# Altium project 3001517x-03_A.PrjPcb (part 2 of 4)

## Sheet 05 - JTAG, SWD, Console, UART, IO expander.SchDoc: JTAG, SWD, Console, UART
size A3; PageSetup: Record=PageOptions¦CenterHorizontal=True¦CenterVertical=True¦PrintScale=0.70¦XCorrection=1.00¦YCorrection=1.00¦PrintKind=0¦BorderSize=5000000¦LeftOffset=0¦BottomOffset=0¦Orientation=2¦PaperLength=4200¦PaperWidth=2970¦Scale=100¦PaperSource=7¦PrintQuality=600¦MediaType=1¦DitherType=10¦PaperKind=A4¦PrintScaleMode=1; Author: Sébastien MEYER; SheetNumber: 5; SheetTotal: 14
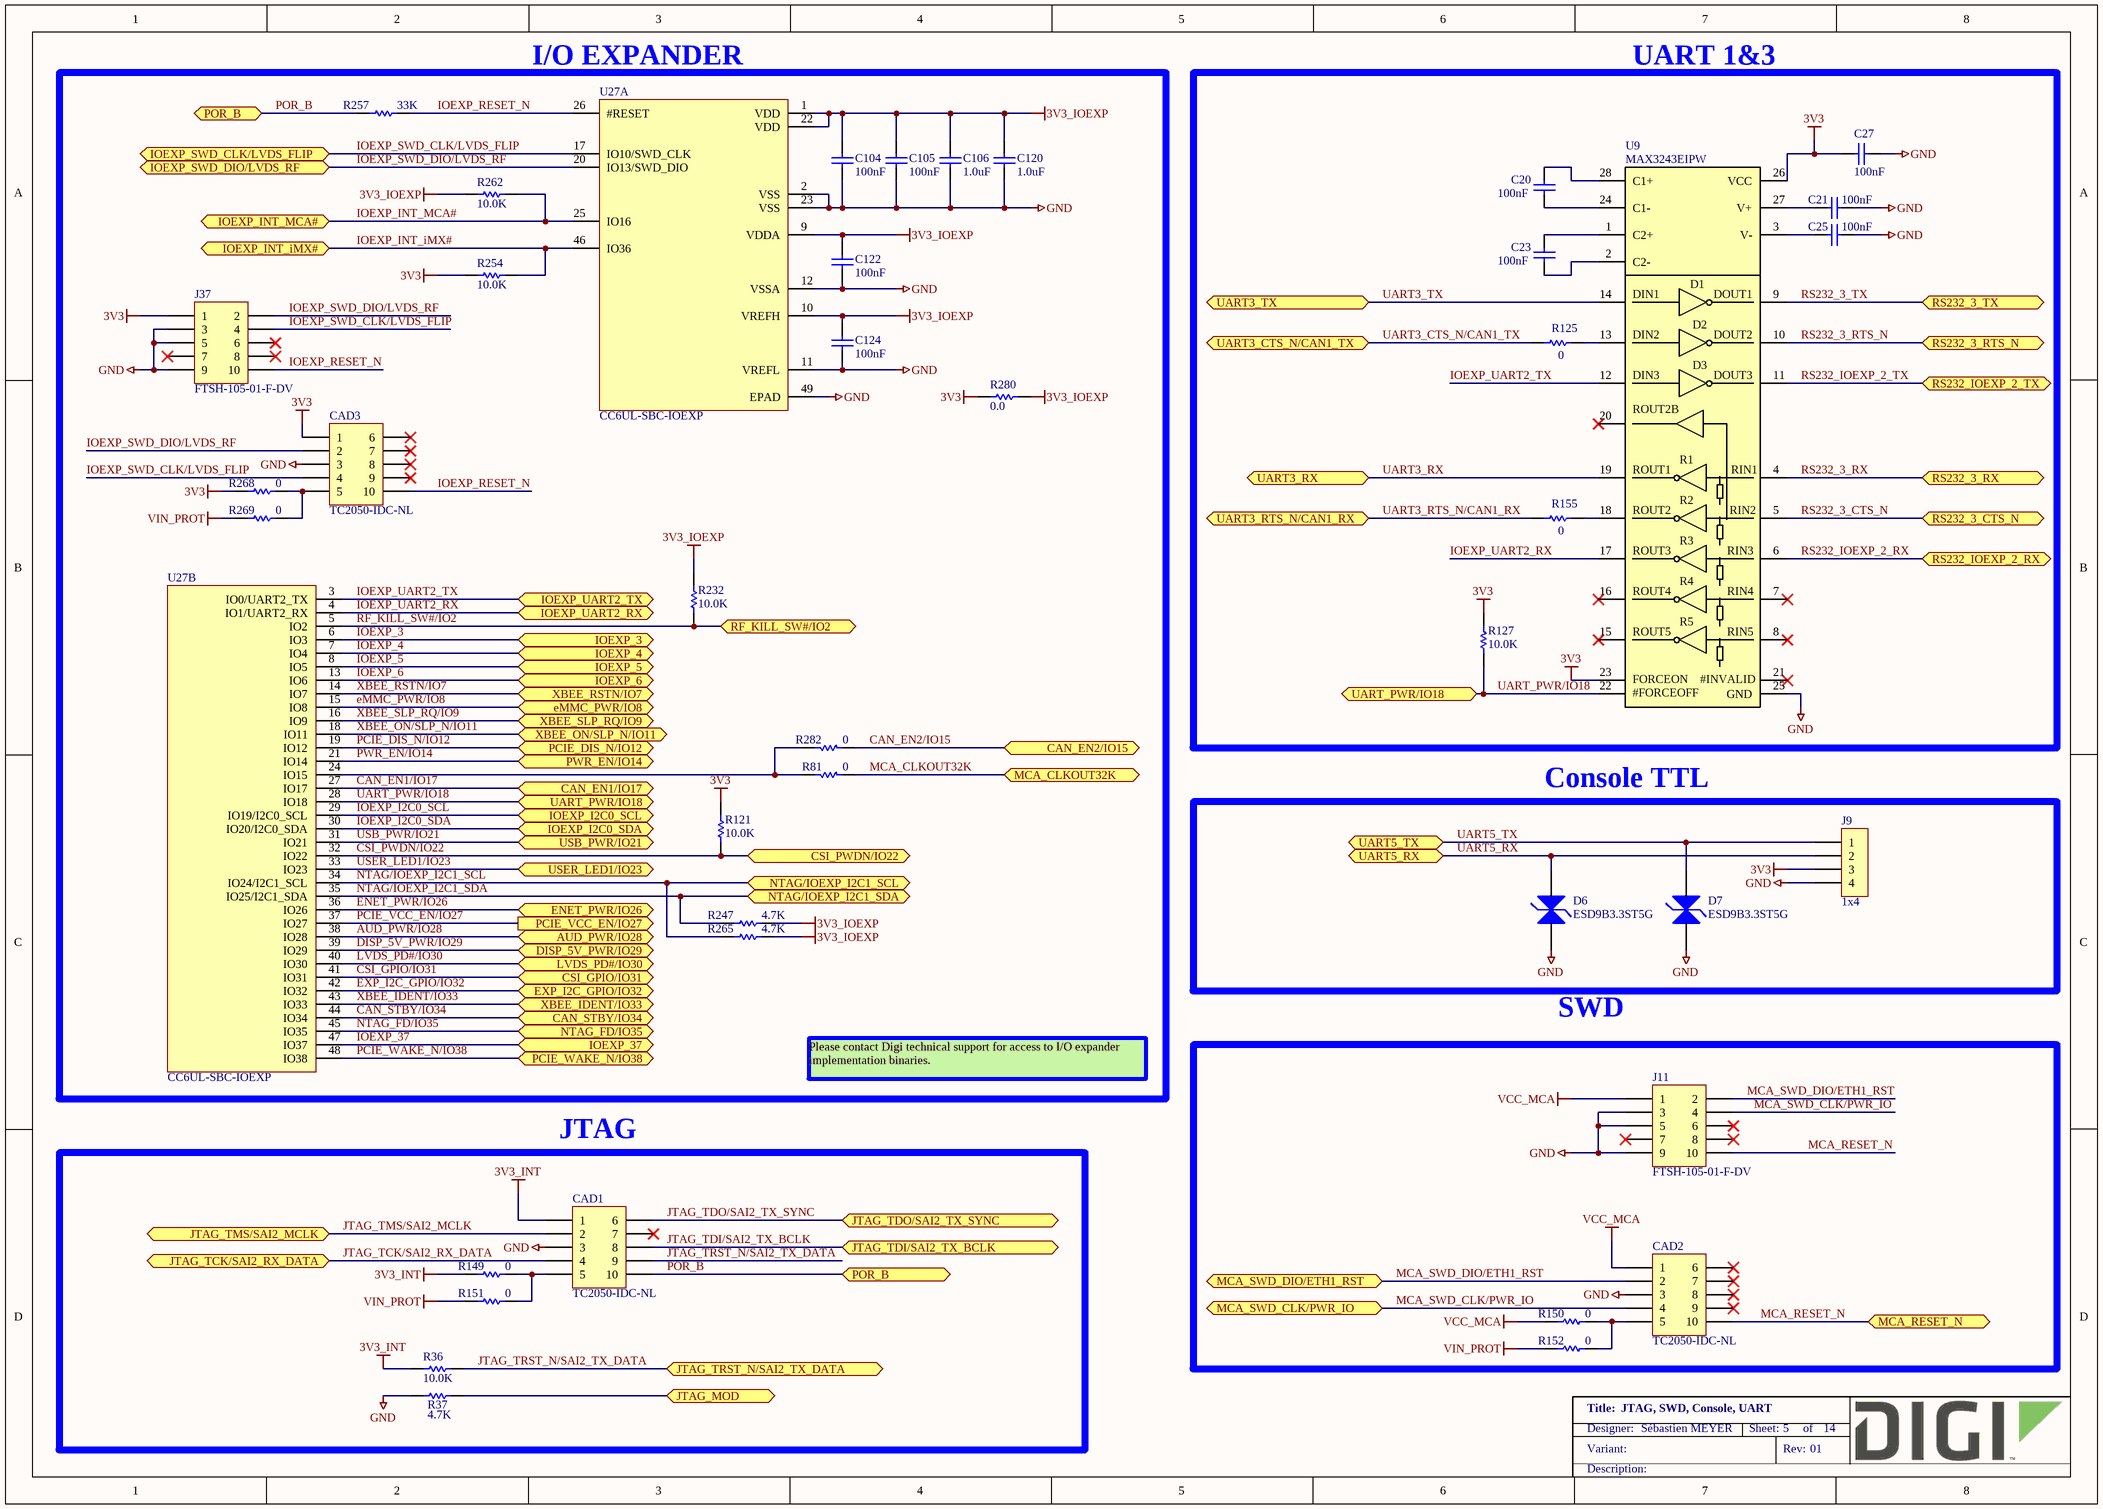
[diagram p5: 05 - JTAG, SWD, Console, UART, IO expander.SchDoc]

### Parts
C20  100nF  [CAPC1005X55N]
C21  100nF  [CAPC1005X55N]
C23  100nF  [CAPC1005X55N]
C25  100nF  [CAPC1005X55N]
C27  100nF  [CAPC1005X55N]
C104  100nF  [CAPC1005X55N]
C105  100nF  [CAPC1005X55N]
C106  1.0uF  [CAPC1005X55AL]
C120  1.0uF  [CAPC1005X55AL]
C122  100nF  [CAPC1005X55N]
C124  100nF  [CAPC1005X55N]
CAD1  TC2050-IDC-NL  [TC_TC2050-IDC-NL]  (no BOM)
CAD2  TC2050-IDC-NL  [TC_TC2050-IDC-NL]  (no BOM)
CAD3  TC2050-IDC-NL  [TC_TC2050-IDC-NL]  (no BOM)
D6  ESD9B3.3ST5G  [SODFL1006X43AN12]
D7  ESD9B3.3ST5G  [SODFL1006X43AN12]
J9  1x4  [MOLEX_53047-0410]
J11  FTSH-105-01-F-DV  [SAMTEC_FTSH-105-01-F-DV]
J37  FTSH-105-01-F-DV  [SAMTEC_FTSH-105-01-F-DV]
R36  10.0K  [RESC1005X40N]
R37  4.7K  [RESC1005X40N]
R81  0  [RESC1005X40N]
R121  10.0K  [RESC1005X40N]
R125  0  [RESC1005X40N]
R127  10.0K  [RESC1005X40N]
R149  0  [RESC1005X40N]
R150  0  [RESC1005X40N]
R151  0  [RESC1005X40N]
R152  0  [RESC1005X40N]
R155  0  [RESC1005X40N]
R232  10.0K  [RESC1005X40N]
R247  4.7K  [RESC1005X40N]
R254  10.0K  [RESC1005X40N]
R257  33K  [RESC1005X40N]
R262  10.0K  [RESC1005X40N]
R265  4.7K  [RESC1005X40N]
R268  0  [RESC1005X40N]
R269  0  [RESC1005X40N]
R280  0.0  [RESC2013X70N]
R282  0  [RESC1005X40N]
U9  MAX3243EIPW  [SOP65P640X120-28N]
U27  CC6UL-SBC-IOEXP  [QFN50P700X700X100-49N]  (parts A,B of 2)

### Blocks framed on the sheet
I/O EXPANDER: C104-C106 C120 C122 C124 CAD3 J37 R81 R121 R232 R247 R254 R257 R262 R265 R268 R269 R280 R282 U27
UART 1&3: C20 C21 C23 C25 C27 R125 R127 R155 U9
Console TTL: D6 D7 J9
JTAG: CAD1 R36 R37 R149 R151

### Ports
AUD_PWR/IO28 (bidir), CAN_EN1/IO17 (bidir), CAN_EN2/IO15 (bidir), CAN_STBY/IO34 (bidir), CSI_GPIO/IO31 (bidir), CSI_PWDN/IO22 (bidir), DISP_5V_PWR/IO29 (bidir), eMMC_PWR/IO8 (bidir), ENET_PWR/IO26 (bidir), EXP_I2C_GPIO/IO32 (bidir), IOEXP_3 (bidir), IOEXP_4 (bidir), IOEXP_5 (bidir), IOEXP_6 (bidir), IOEXP_37 (bidir), IOEXP_I2C0_SCL (bidir), IOEXP_I2C0_SDA (bidir), IOEXP_INT_iMX# (bidir), IOEXP_INT_MCA# (bidir), IOEXP_SWD_CLK/LVDS_FLIP (bidir), IOEXP_SWD_DIO/LVDS_RF (bidir), IOEXP_UART2_RX (bidir), IOEXP_UART2_TX (bidir), JTAG_MOD (bidir), JTAG_TCK/SAI2_RX_DATA (bidir), JTAG_TDI/SAI2_TX_BCLK (bidir), JTAG_TDO/SAI2_TX_SYNC (bidir), JTAG_TMS/SAI2_MCLK (bidir), JTAG_TRST_N/SAI2_TX_DATA (bidir), LVDS_PD#/IO30 (bidir), MCA_CLKOUT32K (bidir), MCA_RESET_N (bidir), MCA_SWD_CLK/PWR_IO (bidir), MCA_SWD_DIO/ETH1_RST (bidir), NTAG/IOEXP_I2C1_SCL (bidir), NTAG/IOEXP_I2C1_SDA (bidir), NTAG_FD/IO35 (bidir), PCIE_DIS_N/IO12 (bidir), PCIE_VCC_EN/IO27 (out), PCIE_WAKE_N/IO38 (bidir), POR_B (bidir), PWR_EN/IO14 (bidir), RF_KILL_SW#/IO2 (bidir), RS232_3_CTS_N (bidir), RS232_3_RTS_N (bidir), RS232_3_RX (bidir), RS232_3_TX (bidir), RS232_IOEXP_2_RX (bidir), RS232_IOEXP_2_TX (bidir), UART3_CTS_N/CAN1_TX (bidir), UART3_RTS_N/CAN1_RX (bidir), UART3_RX (bidir), UART3_TX (bidir), UART5_RX (bidir), UART5_TX (bidir), UART_PWR/IO18 (bidir), USB_PWR/IO21 (bidir), USER_LED1/IO23 (bidir), XBEE_IDENT/IO33 (bidir), XBEE_ON/SLP_N/IO11 (bidir), XBEE_RSTN/IO7 (bidir), XBEE_SLP_RQ/IO9 (bidir)

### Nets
3V3: C27.2 CAD3.1 J9.3 J37.1 R121.2 R127.1 R254.1 R268.1 R280.1 U9.23(FORCEON) U9.26(VCC)
3V3_INT: CAD1.1 R36.2 R149.1
3V3_IOEXP: C104.2 C105.2 C106.2 C120.2 C122.2 C124.2 R232.1 R247.2 R262.2 R265.2 R280.2 U27.1(VDD) U27.9(VDDA) U27.10(VREFH) U27.22(VDD)
GND: C21.1 C25.1 C27.1 C104.1 C105.1 C106.1 C120.1 C122.1 C124.1 CAD1.3 CAD2.3 CAD3.3 D6.1 D7.1 J9.4 J11.3 J11.5 J11.9 J37.3 J37.5 J37.9 R37.1 U9.25(GND) U27.2(VSS) U27.11(VREFL) U27.12(VSSA) U27.23(VSS) U27.49(EPAD)
VCC_MCA: CAD2.1 J11.1 R150.1
VIN_PROT: R151.1 R152.1 R269.1
AUD_PWR/IO28: U27.38(IO28) ; port AUD_PWR/IO28
CAN_EN1/IO17: U27.27(IO17) ; port CAN_EN1/IO17
CAN_EN2/IO15: R282.1 ; port CAN_EN2/IO15
CAN_STBY/IO34: U27.44(IO34) ; port CAN_STBY/IO34
CSI_GPIO/IO31: U27.41(IO31) ; port CSI_GPIO/IO31
CSI_PWDN/IO22: R121.1 U27.32(IO22) ; port CSI_PWDN/IO22
DISP_5V_PWR/IO29: U27.39(IO29) ; port DISP_5V_PWR/IO29
eMMC_PWR/IO8: U27.15(IO8) ; port eMMC_PWR/IO8
ENET_PWR/IO26: U27.36(IO26) ; port ENET_PWR/IO26
EXP_I2C_GPIO/IO32: U27.42(IO32) ; port EXP_I2C_GPIO/IO32
IOEXP_3: U27.6(IO3) ; port IOEXP_3
IOEXP_4: U27.7(IO4) ; port IOEXP_4
IOEXP_5: U27.8(IO5) ; port IOEXP_5
IOEXP_6: U27.13(IO6) ; port IOEXP_6
IOEXP_37: U27.47(IO37) ; port IOEXP_37
IOEXP_I2C0_SCL: U27.29(IO19/I2C0_SCL) ; port IOEXP_I2C0_SCL
IOEXP_I2C0_SDA: U27.30(IO20/I2C0_SDA) ; port IOEXP_I2C0_SDA
IOEXP_INT_iMX#: R254.2 U27.46(IO36) ; port IOEXP_INT_iMX#
IOEXP_INT_MCA#: R262.1 U27.25(IO16) ; port IOEXP_INT_MCA#
IOEXP_RESET_N: CAD3.10 J37.10 R257.2 U27.26(#RESET)
IOEXP_SWD_CLK/LVDS_FLIP: CAD3.4 J37.4 U27.17(IO10/SWD_CLK) ; port IOEXP_SWD_CLK/LVDS_FLIP
IOEXP_SWD_DIO/LVDS_RF: CAD3.2 J37.2 U27.20(IO13/SWD_DIO) ; port IOEXP_SWD_DIO/LVDS_RF
IOEXP_UART2_RX: U9.17(ROUT3) U27.4(IO1/UART2_RX) ; port IOEXP_UART2_RX
IOEXP_UART2_TX: U9.12(DIN3) U27.3(IO0/UART2_TX) ; port IOEXP_UART2_TX
JTAG_MOD: R37.2 ; port JTAG_MOD
JTAG_TCK/SAI2_RX_DATA: CAD1.4 ; port JTAG_TCK/SAI2_RX_DATA
JTAG_TDI/SAI2_TX_BCLK: CAD1.8 ; port JTAG_TDI/SAI2_TX_BCLK
JTAG_TDO/SAI2_TX_SYNC: CAD1.6 ; port JTAG_TDO/SAI2_TX_SYNC
JTAG_TMS/SAI2_MCLK: CAD1.2 ; port JTAG_TMS/SAI2_MCLK
JTAG_TRST_N/SAI2_TX_DATA: CAD1.9 R36.1 ; port JTAG_TRST_N/SAI2_TX_DATA
LVDS_PD#/IO30: U27.40(IO30) ; port LVDS_PD#/IO30
MCA_CLKOUT32K: R81.1 ; port MCA_CLKOUT32K
MCA_RESET_N: CAD2.10 J11.10 ; port MCA_RESET_N
MCA_SWD_CLK/PWR_IO: CAD2.4 J11.4 ; port MCA_SWD_CLK/PWR_IO
MCA_SWD_DIO/ETH1_RST: CAD2.2 J11.2 ; port MCA_SWD_DIO/ETH1_RST
NTAG/IOEXP_I2C1_SCL: R265.1 U27.34(IO24/I2C1_SCL) ; port NTAG/IOEXP_I2C1_SCL
NTAG/IOEXP_I2C1_SDA: R247.1 U27.35(IO25/I2C1_SDA) ; port NTAG/IOEXP_I2C1_SDA
NTAG_FD/IO35: U27.45(IO35) ; port NTAG_FD/IO35
PCIE_DIS_N/IO12: U27.19(IO12) ; port PCIE_DIS_N/IO12
PCIE_VCC_EN/IO27: U27.37(IO27) ; port PCIE_VCC_EN/IO27
PCIE_WAKE_N/IO38: U27.48(IO38) ; port PCIE_WAKE_N/IO38
POR_B: CAD1.10 R257.1 ; port POR_B
PWR_EN/IO14: U27.21(IO14) ; port PWR_EN/IO14
RF_KILL_SW#/IO2: R232.2 U27.5(IO2) ; port RF_KILL_SW#/IO2
RS232_3_CTS_N: U9.5(RIN2) ; port RS232_3_CTS_N
RS232_3_RTS_N: U9.10(DOUT2) ; port RS232_3_RTS_N
RS232_3_RX: U9.4(RIN1) ; port RS232_3_RX
RS232_3_TX: U9.9(DOUT1) ; port RS232_3_TX
RS232_IOEXP_2_RX: U9.6(RIN3) ; port RS232_IOEXP_2_RX
RS232_IOEXP_2_TX: U9.11(DOUT3) ; port RS232_IOEXP_2_TX
UART3_CTS_N/CAN1_TX: R125.1 ; port UART3_CTS_N/CAN1_TX
UART3_RTS_N/CAN1_RX: R155.1 ; port UART3_RTS_N/CAN1_RX
UART3_RX: U9.19(ROUT1) ; port UART3_RX
UART3_TX: U9.14(DIN1) ; port UART3_TX
UART5_RX: D6.2 J9.2 ; port UART5_RX
UART5_TX: D7.2 J9.1 ; port UART5_TX
UART_PWR/IO18: R127.2 U9.22(#FORCEOFF) U27.28(IO18) ; port UART_PWR/IO18
USB_PWR/IO21: U27.31(IO21) ; port USB_PWR/IO21
USER_LED1/IO23: U27.33(IO23) ; port USER_LED1/IO23
XBEE_IDENT/IO33: U27.43(IO33) ; port XBEE_IDENT/IO33
XBEE_ON/SLP_N/IO11: U27.18(IO11) ; port XBEE_ON/SLP_N/IO11
XBEE_RSTN/IO7: U27.14(IO7) ; port XBEE_RSTN/IO7
XBEE_SLP_RQ/IO9: U27.16(IO9) ; port XBEE_SLP_RQ/IO9
NetC20_1: C20.1 U9.24(C1-)
NetC20_2: C20.2 U9.28(C1+)
NetC21_2: C21.2 U9.27(V+)
NetC23_1: C23.1 U9.2(C2-)
NetC23_2: C23.2 U9.1(C2+)
NetC25_2: C25.2 U9.3(V-)
NetCAD1_5: CAD1.5 R149.2 R151.2
NetCAD2_5: CAD2.5 R150.2 R152.2
NetCAD3_5: CAD3.5 R268.2 R269.2
NetR81_2: R81.2 R282.2 U27.24(IO15)
NetR125_2: R125.2 U9.13(DIN2)
NetR155_2: R155.2 U9.18(ROUT2)

Not connected (* = marked no-connect by the designer): CAD1 7*; CAD2 6* 7* 8* 9*; CAD3 6* 7* 8* 9*; J11 6* 7* 8*; J37 6* 7* 8*; U9 7(RI4N)* 8(RIN5)* 15(ROUT5)* 16(ROUT4)* 20(#R2OUT)* 21(#INVALID)*

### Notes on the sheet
- SWD
- Please contact Digi technical support for access to I/O expander implementation binaries.

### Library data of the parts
C20 C21 C23 C25 C27 C104 C105 C122 C124 = 1000006: CAP 100nF 16V 10% X7R 0402; Part_Type: Capacitor; Manufacturer: Murata; Manufacturer_Part_Number: GRM155R71C104KA88D; Component_Life_Cycle_State: CAD Reviewed; Area: 0.95; Project: KITT; Tolerance: 10; Digi_PN: 14050552
C106 C120 = 1000073: CAP CER 1UF 6.3V 20% X5R 0402; Part_Type: Capacitor; Manufacturer: Murata; Manufacturer_Part_Number: GRM155R60J105ME19D; Digi_PN: 14050543; Component_Life_Cycle_State: Proven; Area: 0.95; Project: Adjustable Foundation; Voltage: 6.3
CAD1-CAD3 = CAD0066: CBL PLUG-OF-NAILS 10-PIN; Part_Type: Test Point; Component_Life_Cycle_State: Created; Area: 8; Project: CCWMX6_SBC board
D6 D7 = 1001637: TVS DIODE 3.3VWM SOD923; Part_Type: Diodes; Manufacturer: On Semiconductor; Digi_PN: 17050883; Component_Life_Cycle_State: Reviewed; Area: 1,01; Project: CareTaker IV
J9 = 1001137: CONN HEADER 4POS 1.25MM VERT TIN; Part_Type: Connector; Manufacturer: Molex; Manufacturer_Part_Number: 53047-0410; Digi_PN: 18050344; Component_Life_Cycle_State: Reviewed; Area: 21,6; Project: CCWMX6_SBC board
J11 J37 = 1000034: CONN HEADER 10POS DUAL .05" SMD; Part_Type: Connector; Manufacturer: Samtec; Note: 18000715 = Digi No. for GE WDNU; Digi_PN: 18000539; Component_Life_Cycle_State: Proven; Area: 43,55; Project: Adjustable Foundation
R36 R121 R127 R232 R254 R262 = 1000537: RES 10.0K OHM 1/10W 1% 0402 SMD; Part_Type: Resistor; Manufacturer: Panasonic - ECG; Manufacturer_Part_Number: ERJ-2RKF1002X; Component_Life_Cycle_State: CAD Reviewed; Area: 0.95; Project: KITT; Power_WV_SRF: 100; Digi_PN: 13051084
R37 R247 R265 = 1000038: RES 4.7K OHM 1/10W 5% 0402 SMD; Part_Type: Resistor; Manufacturer: Panasonic - ECG; Manufacturer_Part_Number: ERJ-2GEJ472X; Component_Life_Cycle_State: Proven; Area: 0.95; Project: Adjustable Foundation; Power_WV_SRF: 100; Tolerance: 5; Digi_PN: 13050549
R81 R125 R149-R152 R155 R268 R269 R282 = 1000076: RES 0.0 OHM 1/10W 0402 SMD; Part_Type: Resistor; Manufacturer: Panasonic - ECG; Manufacturer_Part_Number: ERJ-2GE0R00X; Component_Life_Cycle_State: Proven; Area: 0.95; Project: Adjustable Foundation; Power_WV_SRF: 10; Digi_PN: 13050387
R257 = 1002118: RES SMD 33K OHM 1% 1/16W 0402; Part_Type: Resistor; Manufacturer: Panasonic - ECG; Manufacturer_Part_Number: ERJ-2RKF3302X; Component_Life_Cycle_State: Created; Area: 2,2; Project: iMX6UL+PMIC; Digi_PN: 13051142
R280 = 1001557: RES 0.0 OHM 1/8W JUMP 0805 SMD; Part_Type: Resistor; Manufacturer: Yageo; Manufacturer_Part_Number: RC0805JR-070RL; Note: 13051095 = Digi No. for GE WDNU; Digi_PN: TR00037; Component_Life_Cycle_State: Reviewed; Area: 5.8; Project: WDNU-II; Power_WV_SRF: 125
U9 = 1001499: IC RS232 3V-5.5V DRVR 28-TSSOP; Manufacturer: Texas Instruments; Digi_PN: 16050972; Component_Life_Cycle_State: Reviewed; Area: 67; Project: CCWMX6_SBC board
U27 = 1002077: KINETIS KL14, 32FL/4SR, -40/+105°C, QFN48; Part_Type: IC; Manufacturer: Freescale Semiconductor; Manufacturer_Part_Number: MKL14Z32VFT4; Digi_PN: 16051854; Component_Life_Cycle_State: Created; Area: 60,84; Project: iMX6UL+PMIC

## Sheet 06 - Ethernet.SchDoc: 2x 10/100M Ethernet
size A3; PageSetup: Record=PageOptions¦CenterHorizontal=True¦CenterVertical=True¦PrintScale=0.70¦XCorrection=1.00¦YCorrection=1.00¦PrintKind=0¦BorderSize=5000000¦LeftOffset=0¦BottomOffset=0¦Orientation=2¦PaperLength=4200¦PaperWidth=2970¦Scale=100¦PaperSource=7¦PrintQuality=600¦MediaType=1¦DitherType=10¦PaperKind=A4¦PrintScaleMode=1; Author: Sébastien MEYER; SheetNumber: 6; SheetTotal: 14
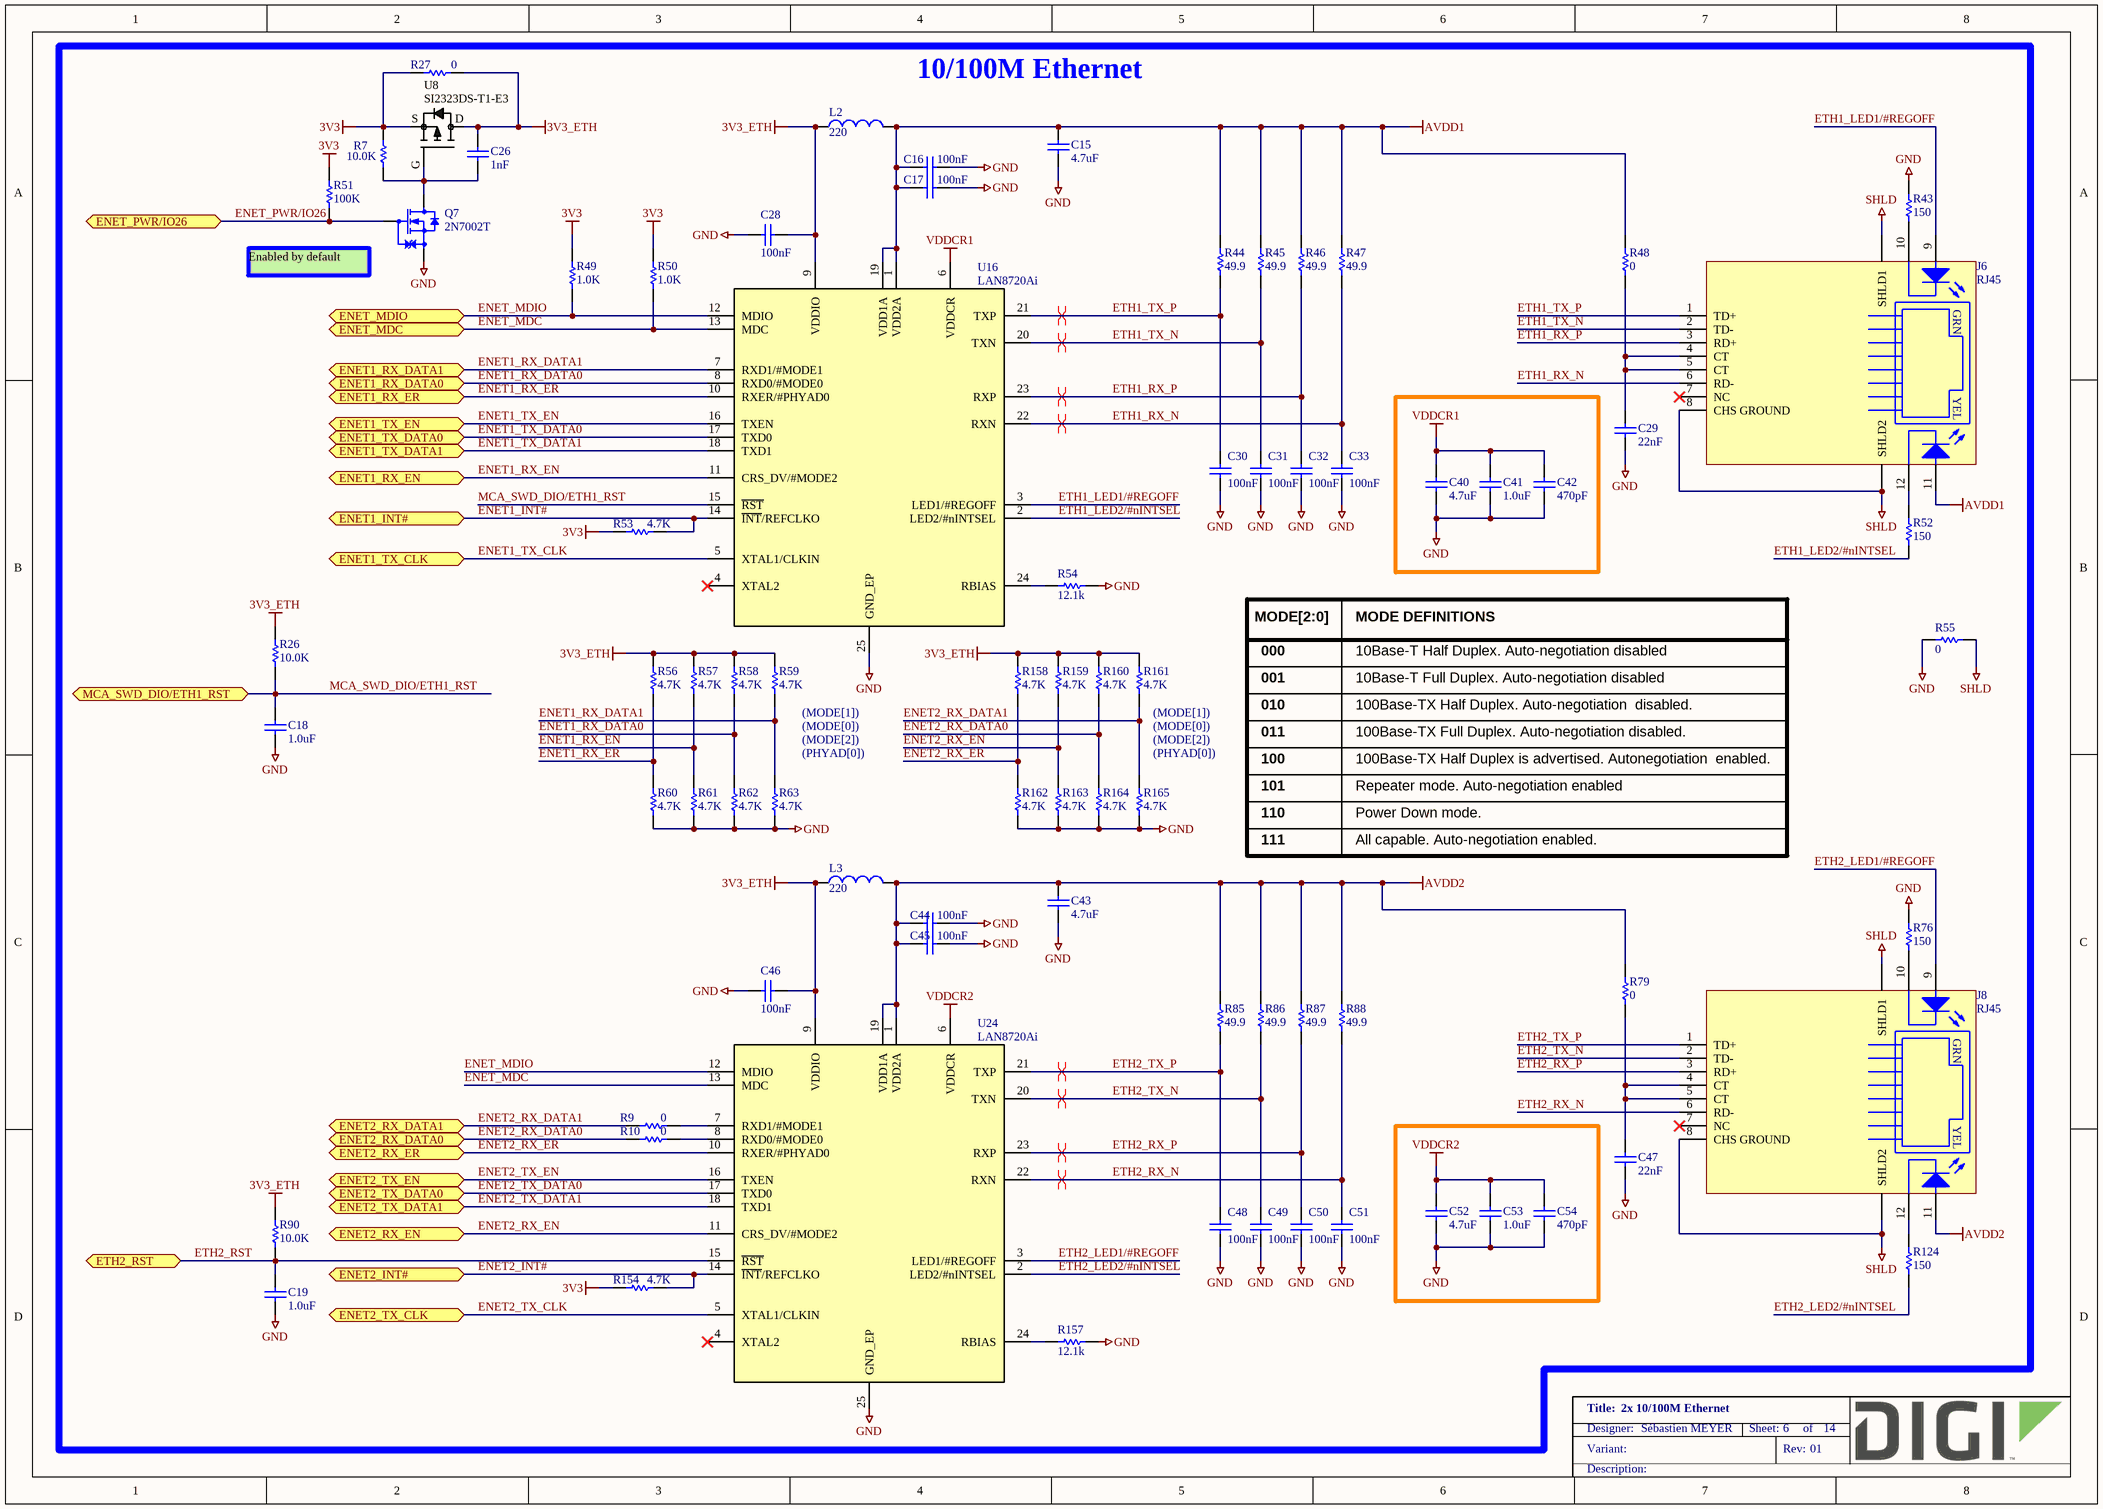
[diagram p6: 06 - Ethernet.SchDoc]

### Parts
C15  4.7uF  [CAPC2013X135N]
C16  100nF  [CAPC1005X55N]
C17  100nF  [CAPC1005X55N]
C18  1.0uF  [CAPC1005X55N]
C19  1.0uF  [CAPC1005X55N]
C26  1nF  [CAPC1005X55N]
C28  100nF  [CAPC1005X55N]
C29  22nF  [CAPC1608X90N]
C30  100nF  [CAPC1005X55N]
C31  100nF  [CAPC1005X55N]
C32  100nF  [CAPC1005X55N]
C33  100nF  [CAPC1005X55N]
C40  4.7uF  [CAPC2013X135N]
C41  1.0uF  [CAPC1005X55N]
C42  470pF  [CAPC1005X55N]
C43  4.7uF  [CAPC2013X135N]
C44  100nF  [CAPC1005X55N]
C45  100nF  [CAPC1005X55N]
C46  100nF  [CAPC1005X55N]
C47  22nF  [CAPC1608X90N]
C48  100nF  [CAPC1005X55N]
C49  100nF  [CAPC1005X55N]
C50  100nF  [CAPC1005X55N]
C51  100nF  [CAPC1005X55N]
C52  4.7uF  [CAPC2013X135N]
C53  1.0uF  [CAPC1005X55N]
C54  470pF  [CAPC1005X55N]
J6  RJ45  [XMultiple_XMG-9799-8821]
J8  RJ45  [XMultiple_XMG-9799-8821]
L2  220  [INDC2013X110N]
L3  220  [INDC2013X110N]
Q7  2N7002T  [SOTFL50P160X80_GSD-3N]
R7  10.0K  [RESC1005X40N]
R9  0  [RESC1005X40N]
R10  0  [RESC1005X40N]
R26  10.0K  [RESC1005X40N]
R27  0  [RESC1609X55N]
R43  150  [RESC1005X40N]
R44  49.9  [RESC1005X40N]
R45  49.9  [RESC1005X40N]
R46  49.9  [RESC1005X40N]
R47  49.9  [RESC1005X40N]
R48  0  [RESC1609X55N]
R49  1.0K  [RESC1005X40N]
R50  1.0K  [RESC1005X40N]
R51  100K  [RESC1005X40N]
R52  150  [RESC1005X40N]
R53  4.7K  [RESC1005X40N]
R54  12.1k  [RESC1005X40N]
R55  0  [RESC3225X60N]
R56  4.7K  [RESC1005X40N]
R57  4.7K  [RESC1005X40N]
R58  4.7K  [RESC1005X40N]
R59  4.7K  [RESC1005X40N]
R60  4.7K  [RESC1005X40N]
R61  4.7K  [RESC1005X40N]
R62  4.7K  [RESC1005X40N]
R63  4.7K  [RESC1005X40N]
R76  150  [RESC1005X40N]
R79  0  [RESC1609X55N]
R85  49.9  [RESC1005X40N]
R86  49.9  [RESC1005X40N]
R87  49.9  [RESC1005X40N]
R88  49.9  [RESC1005X40N]
R90  10.0K  [RESC1005X40N]
R124  150  [RESC1005X40N]
R154  4.7K  [RESC1005X40N]
R157  12.1k  [RESC1005X40N]
R158  4.7K  [RESC1005X40N]
R159  4.7K  [RESC1005X40N]
R160  4.7K  [RESC1005X40N]
R161  4.7K  [RESC1005X40N]
R162  4.7K  [RESC1005X40N]
R163  4.7K  [RESC1005X40N]
R164  4.7K  [RESC1005X40N]
R165  4.7K  [RESC1005X40N]
U8  SI2323DS-T1-E3  [SOT95P240X110_GSD-3N]
U16  LAN8720Ai  [QFN50P400X400X100-25]
U24  LAN8720Ai  [QFN50P400X400X100-25]

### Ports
ENET1_INT# (bidir), ENET1_RX_DATA0 (bidir), ENET1_RX_DATA1 (bidir), ENET1_RX_EN (bidir), ENET1_RX_ER (bidir), ENET1_TX_CLK (bidir), ENET1_TX_DATA0 (bidir), ENET1_TX_DATA1 (bidir), ENET1_TX_EN (bidir), ENET2_INT# (bidir), ENET2_RX_DATA0 (bidir), ENET2_RX_DATA1 (bidir), ENET2_RX_EN (bidir), ENET2_RX_ER (bidir), ENET2_TX_CLK (bidir), ENET2_TX_DATA0 (bidir), ENET2_TX_DATA1 (bidir), ENET2_TX_EN (bidir), ENET_MDC (bidir), ENET_MDIO (bidir), ENET_PWR/IO26 (bidir), ETH2_RST (bidir), MCA_SWD_DIO/ETH1_RST (bidir)

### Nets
3V3: R7.1 R27.1 R49.1 R50.1 R51.1 R53.2 R154.2 U8.S
3V3_ETH: C26.2 C28.1 C46.1 L2.1 L3.1 R26.1 R27.2 R56.1 R57.1 R58.1 R59.1 R90.1 R158.1 R159.1 R160.1 R161.1 U8.D U16.9(VDDIO) U24.9(VDDIO)
AVDD1: C15.2 C16.2 C17.1 J6.11 L2.2 R44.2 R45.2 R46.2 R47.2 R48.2 U16.1(VDD2A) U16.19(VDD1A)
AVDD2: C43.2 C44.2 C45.1 J8.11 L3.2 R79.2 R85.2 R86.2 R87.2 R88.2 U24.1(VDD2A) U24.19(VDD1A)
GND: C15.1 C16.1 C17.2 C18.1 C19.1 C28.2 C29.1 C30.2 C31.2 C32.2 C33.2 C40.1 C41.1 C42.1 C43.1 C44.1 C45.2 C46.2 C47.1 C48.2 C49.2 C50.2 C51.2 C52.1 C53.1 C54.1 Q7.S R43.2 R54.1 R55.1 R60.2 R61.2 R62.2 R63.2 R76.2 R157.1 R162.2 R163.2 R164.2 R165.2 U16.25(GND_EP) U24.25(GND_EP)
SHLD: J6.8(CHS_GROUND) J6.SHLD1 J6.SHLD2 J8.8(CHS_GROUND) J8.SHLD1 J8.SHLD2 R55.2
VDDCR1: C40.2 C41.2 C42.2 U16.6(VDDCR)
VDDCR2: C52.2 C53.2 C54.2 U24.6(VDDCR)
ENET1_INT#: R53.1 U16.14(~{INT}/REFCLKO) ; port ENET1_INT#
ENET1_RX_DATA0: R58.2 R62.1 U16.8(RXD0/#MODE0) ; port ENET1_RX_DATA0
ENET1_RX_DATA1: R59.2 R63.1 U16.7(RXD1/#MODE1) ; port ENET1_RX_DATA1
ENET1_RX_EN: R57.2 R61.1 U16.11(CRS_DV/#MODE2) ; port ENET1_RX_EN
ENET1_RX_ER: R56.2 R60.1 U16.10(RXER/#PHYAD0) ; port ENET1_RX_ER
ENET1_TX_CLK: U16.5(XTAL1/CLKIN) ; port ENET1_TX_CLK
ENET1_TX_DATA0: U16.17(TXD0) ; port ENET1_TX_DATA0
ENET1_TX_DATA1: U16.18(TXD1) ; port ENET1_TX_DATA1
ENET1_TX_EN: U16.16(TXEN) ; port ENET1_TX_EN
ENET2_INT#: R154.1 U24.14(~{INT}/REFCLKO) ; port ENET2_INT#
ENET2_RX_DATA0: R10.1 R160.2 R164.1 ; port ENET2_RX_DATA0
ENET2_RX_DATA1: R9.1 R161.2 R165.1 ; port ENET2_RX_DATA1
ENET2_RX_EN: R159.2 R163.1 U24.11(CRS_DV/#MODE2) ; port ENET2_RX_EN
ENET2_RX_ER: R158.2 R162.1 U24.10(RXER/#PHYAD0) ; port ENET2_RX_ER
ENET2_TX_CLK: U24.5(XTAL1/CLKIN) ; port ENET2_TX_CLK
ENET2_TX_DATA0: U24.17(TXD0) ; port ENET2_TX_DATA0
ENET2_TX_DATA1: U24.18(TXD1) ; port ENET2_TX_DATA1
ENET2_TX_EN: U24.16(TXEN) ; port ENET2_TX_EN
ENET_MDC: R50.2 U16.13(MDC) U24.13(MDC) ; port ENET_MDC
ENET_MDIO: R49.2 U16.12(MDIO) U24.12(MDIO) ; port ENET_MDIO
ENET_PWR/IO26: Q7.G R51.2 ; port ENET_PWR/IO26
ETH1_LED1/#REGOFF: J6.9 U16.3(LED1/#REGOFF)
ETH1_LED2/#nINTSEL: R52.1 U16.2(LED2/#nINTSEL)
ETH1_RX_N: C33.1 J6.6(RD-) R47.1 U16.22(RXN)
ETH1_RX_P: C32.1 J6.3(RD+) R46.1 U16.23(RXP)
ETH1_TX_N: C31.1 J6.2(TD-) R45.1 U16.20(TXN)
ETH1_TX_P: C30.1 J6.1(TD+) R44.1 U16.21(TXP)
ETH2_LED1/#REGOFF: J8.9 U24.3(LED1/#REGOFF)
ETH2_LED2/#nINTSEL: R124.1 U24.2(LED2/#nINTSEL)
ETH2_RST: C19.2 R90.2 U24.15(~{RST}) ; port ETH2_RST
ETH2_RX_N: C51.1 J8.6(RD-) R88.1 U24.22(RXN)
ETH2_RX_P: C50.1 J8.3(RD+) R87.1 U24.23(RXP)
ETH2_TX_N: C49.1 J8.2(TD-) R86.1 U24.20(TXN)
ETH2_TX_P: C48.1 J8.1(TD+) R85.1 U24.21(TXP)
MCA_SWD_DIO/ETH1_RST: C18.2 R26.2 U16.15(~{RST}) ; port MCA_SWD_DIO/ETH1_RST
NetC26_1: C26.1 Q7.D R7.2 U8.G
NetC29_2: C29.2 J6.4(CT) J6.5(CT) R48.1
NetC47_2: C47.2 J8.4(CT) J8.5(CT) R79.1
NetJ6_10: J6.10 R43.1
NetJ6_12: J6.12 R52.2
NetJ8_10: J8.10 R76.1
NetJ8_12: J8.12 R124.2
NetR9_2: R9.2 U24.7(RXD1/#MODE1)
NetR10_2: R10.2 U24.8(RXD0/#MODE0)
NetR54_2: R54.2 U16.24(RBIAS)
NetR157_2: R157.2 U24.24(RBIAS)

Not connected (* = marked no-connect by the designer): J6 7(NC)*; J8 7(NC)*; U16 4(XTAL2)*; U24 4(XTAL2)*

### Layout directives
differential pair: ETH1_RX_N, ETH1_RX_P, ETH1_TX_N, ETH1_TX_P, ETH2_RX_N, ETH2_RX_P, ETH2_TX_N, ETH2_TX_P

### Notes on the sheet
- 10/100M Ethernet
- Enabled by default
- MODE[2:0]
- MODE DEFINITIONS
- (near R59) (MODE[1])
- (near R161) (MODE[1])
- 000
- 001
- 010
- 10Base-T Half Duplex. Auto-negotiation disabled
- 10Base-T Full Duplex. Auto-negotiation disabled
- 100Base-TX Half Duplex. Auto-negotiation  disabled.
- (PHYAD[0])
- (MODE[0])
- (MODE[2])
- (near R165) (PHYAD[0])
- (near R161) (MODE[0])
- 011
- 100
- 100Base-TX Full Duplex. Auto-negotiation disabled.
- 100Base-TX Half Duplex is advertised. Autonegotiation  enabled.
- 101
- 110
- 111
- Repeater mode. Auto-negotiation enabled
- Power Down mode.
- All capable. Auto-negotiation enabled.

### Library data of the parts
C15 C40 C43 C52 = 1000500: CAP CER 4.7UF 25V 10% X5R 0805; Part_Type: Capacitor; Manufacturer: Murata; Manufacturer_Part_Number: GRM21BR61E475KA12L; Component_Life_Cycle_State: Reviewed; Area: 4.24; Project: SDR Prototype RF Board; Digi_PN: 14050307
C16 C17 C28 C30-C33 C44-C46 C48-C51 = 1000006: as C20 on sheet 05 - JTAG, SWD, Console, UART, IO expander
C18 C19 C41 C53 = 1001167: CAP CER 1UF 10V 10% X5R 0402; Part_Type: Capacitor; Manufacturer: Murata; Manufacturer_Part_Number: GRM155R61A105KE15D; Digi_PN: 14050399; Component_Life_Cycle_State: Reviewed; Area: 0.95; Project: CCWMX6_SBC board
C26 = 1000067: CAP CER 1000PF 50V 10% X7R 0402; Part_Type: Capacitor; Manufacturer: Murata; Manufacturer_Part_Number: GRM155R71H102KA01D; Digi_PN: 14050737; Component_Life_Cycle_State: Proven; Area: 0,95; Project: Adjustable Foundation
C29 C47 = 1001024: CAP CER 0.022UF 100V X7R 0603; Part_Type: Capacitor; Manufacturer: TDK Corporation; Manufacturer_Part_Number: C1608X7R2A223M080AA; Digi_PN: 14050726; Component_Life_Cycle_State: Reviewed; Area: 2,27; Project: ResMed RF Test Interface Board
C42 C54 = 1001576: CAP CER 470PF 50V 5% NP0 0402; Part_Type: Capacitor; Manufacturer: Murata; Manufacturer_Part_Number: GRM1555C1H471JA01J; Digi_PN: 14050366; Component_Life_Cycle_State: Reviewed; Area: 0,95; Project: WDNU-II; Tolerance: +/- 5%
J6 J8 = 1001971: CONN, RJ45 100BASE-T R/A, -40/85C; Part_Type: Connector; Manufacturer: XMultiple; Manufacturer_Part_Number: XMG-9799-8821-100D-L1TO-H-HIM; Component_Life_Cycle_State: Reviewed; Area: 337; Project: iMX6UL+PMIC; Digi_PN: 18000733
L2 L3 = 1001174: FERRITE BEAD 220 OHM 2.0A 0805; Manufacturer: Wurth Electronics Inc; Manufacturer_Part_Number: 742792022; Digi_PN: 21000146; Component_Life_Cycle_State: Reviewed; Area: 4.24; Project: CCWMX6_SBC board
Q7 = 1000715: MOSFET N-CH 60V 115MA SOT-523F; Part_Type: Transistor; Manufacturer: Fairchild Semiconductor; Digi_PN: 17050797; Component_Life_Cycle_State: CAD Reviewed; Area: 3.06; Project: SmartMeter2; Note: 17050841 = Digi No. for GE WDNU
R7 R26 R90 = 1000537: as R36 on sheet 05 - JTAG, SWD, Console, UART, IO expander
R9 R10 = 1000076: as R81 on sheet 05 - JTAG, SWD, Console, UART, IO expander
R27 R48 R79 = 1000208: RES 0.0 OHM 1/10W 0603; Part_Type: Resistor; Manufacturer: Panasonic - ECG; Manufacturer_Part_Number: ERJ-3GEY0R00V; Note: 13051103 = Digi No. for GE WDNU; Digi_PN: 13050568; Component_Life_Cycle_State: Reviewed; Area: 2.5; Project: Adjustable Foundation; Voltage: 75V
R43 R52 R76 R124 = 1000465: RES 150 OHM 1/10W 1% 0402 SMD; Part_Type: Resistor; Manufacturer: Panasonic - ECG; Manufacturer_Part_Number: ERJ-2RKF1500X; Digi_PN: 13050557; Component_Life_Cycle_State: CAD Reviewed; Area: 0.95; Project: KITT; Power_WV_SRF: 100
R44-R47 R85-R88 = 1000466: RES 49.9 OHM 1/10W 1% 0402 SMD; Part_Type: Resistor; Manufacturer: Panasonic - ECG; Manufacturer_Part_Number: ERJ-2RKF49R9X; Digi_PN: 13051083; Component_Life_Cycle_State: CAD Reviewed; Area: 0,95; Project: KITT; Power_WV_SRF: 100
R49 R50 = 1000079: RES 1.00K OHM 1/10W 1% 0402 SMD; Part_Type: Resistor; Manufacturer: Panasonic - ECG; Manufacturer_Part_Number: ERJ-2RKF1001X; Digi_PN: 13051085; Component_Life_Cycle_State: Proven; Area: 0.95; Project: Adjustable Foundation; Power_WV_SRF: 10
R51 = 1000480: RES 100K OHM 1/10W 1% 0402 SMD; Part_Type: Resistor; Manufacturer: Panasonic - ECG; Manufacturer_Part_Number: ERJ-2RKF1003X; Digi_PN: 13051063; Component_Life_Cycle_State: CAD Reviewed; Area: 0.95; Project: KITT; Power_WV_SRF: 100
R53 R56-R63 R154 R158-R165 = 1000038: as R37 on sheet 05 - JTAG, SWD, Console, UART, IO expander
R54 R157 = 1000828: RES 12.1K OHM 1/10W 1% 0402 SMD; Part_Type: Resistor; Manufacturer: Panasonic - ECG; Manufacturer_Part_Number: ERJ-2RKF1212X; Component_Life_Cycle_State: Reviewed; Area: 0.95; Project: SmartMeter2; Power_WV_SRF: 100; Digi_PN: 13051088
R55 = 1000229: RES 0.0 OHM 1/2W 1210 SMD; Part_Type: Resistor; Manufacturer: Vishay Dale; Manufacturer_Part_Number: CRCW12100000Z0EA; Digi_PN: 13050962; Component_Life_Cycle_State: Proven; Area: 11,07; Project: Adjustable Foundation
U8 = 1001163: MOSFET P-CH 20V 3.7A SOT23-3; Part_Type: IC; Manufacturer: Vishay Siliconix; Digi_PN: 17050358; Component_Life_Cycle_State: Reviewed; Area: 10.92; Project: CCWMX6_SBC board
U16 U24 = 1001970: TXRX ETHERNET 10/100 24VQFN; Part_Type: IC; Manufacturer: Micrel; Manufacturer_Part_Number: LAN8720Ai-CP-TR; Digi_PN: 16052022; Component_Life_Cycle_State: Created; Area: 16; Project: iMX6UL+PMIC

## Sheet 07 - USB OTG, USB HUB, USB Host.SchDoc: USB OTG, USB Hub, USB Host
size A3; PageSetup: Record=PageOptions¦CenterHorizontal=True¦CenterVertical=True¦PrintScale=0.70¦XCorrection=1.00¦YCorrection=1.00¦PrintKind=0¦BorderSize=5000000¦LeftOffset=0¦BottomOffset=0¦Orientation=2¦PaperLength=4200¦PaperWidth=2970¦Scale=100¦PaperSource=7¦PrintQuality=600¦MediaType=1¦DitherType=10¦PaperKind=A4¦PrintScaleMode=1; Author: Sébastien MEYER; SheetNumber: 7; SheetTotal: 14
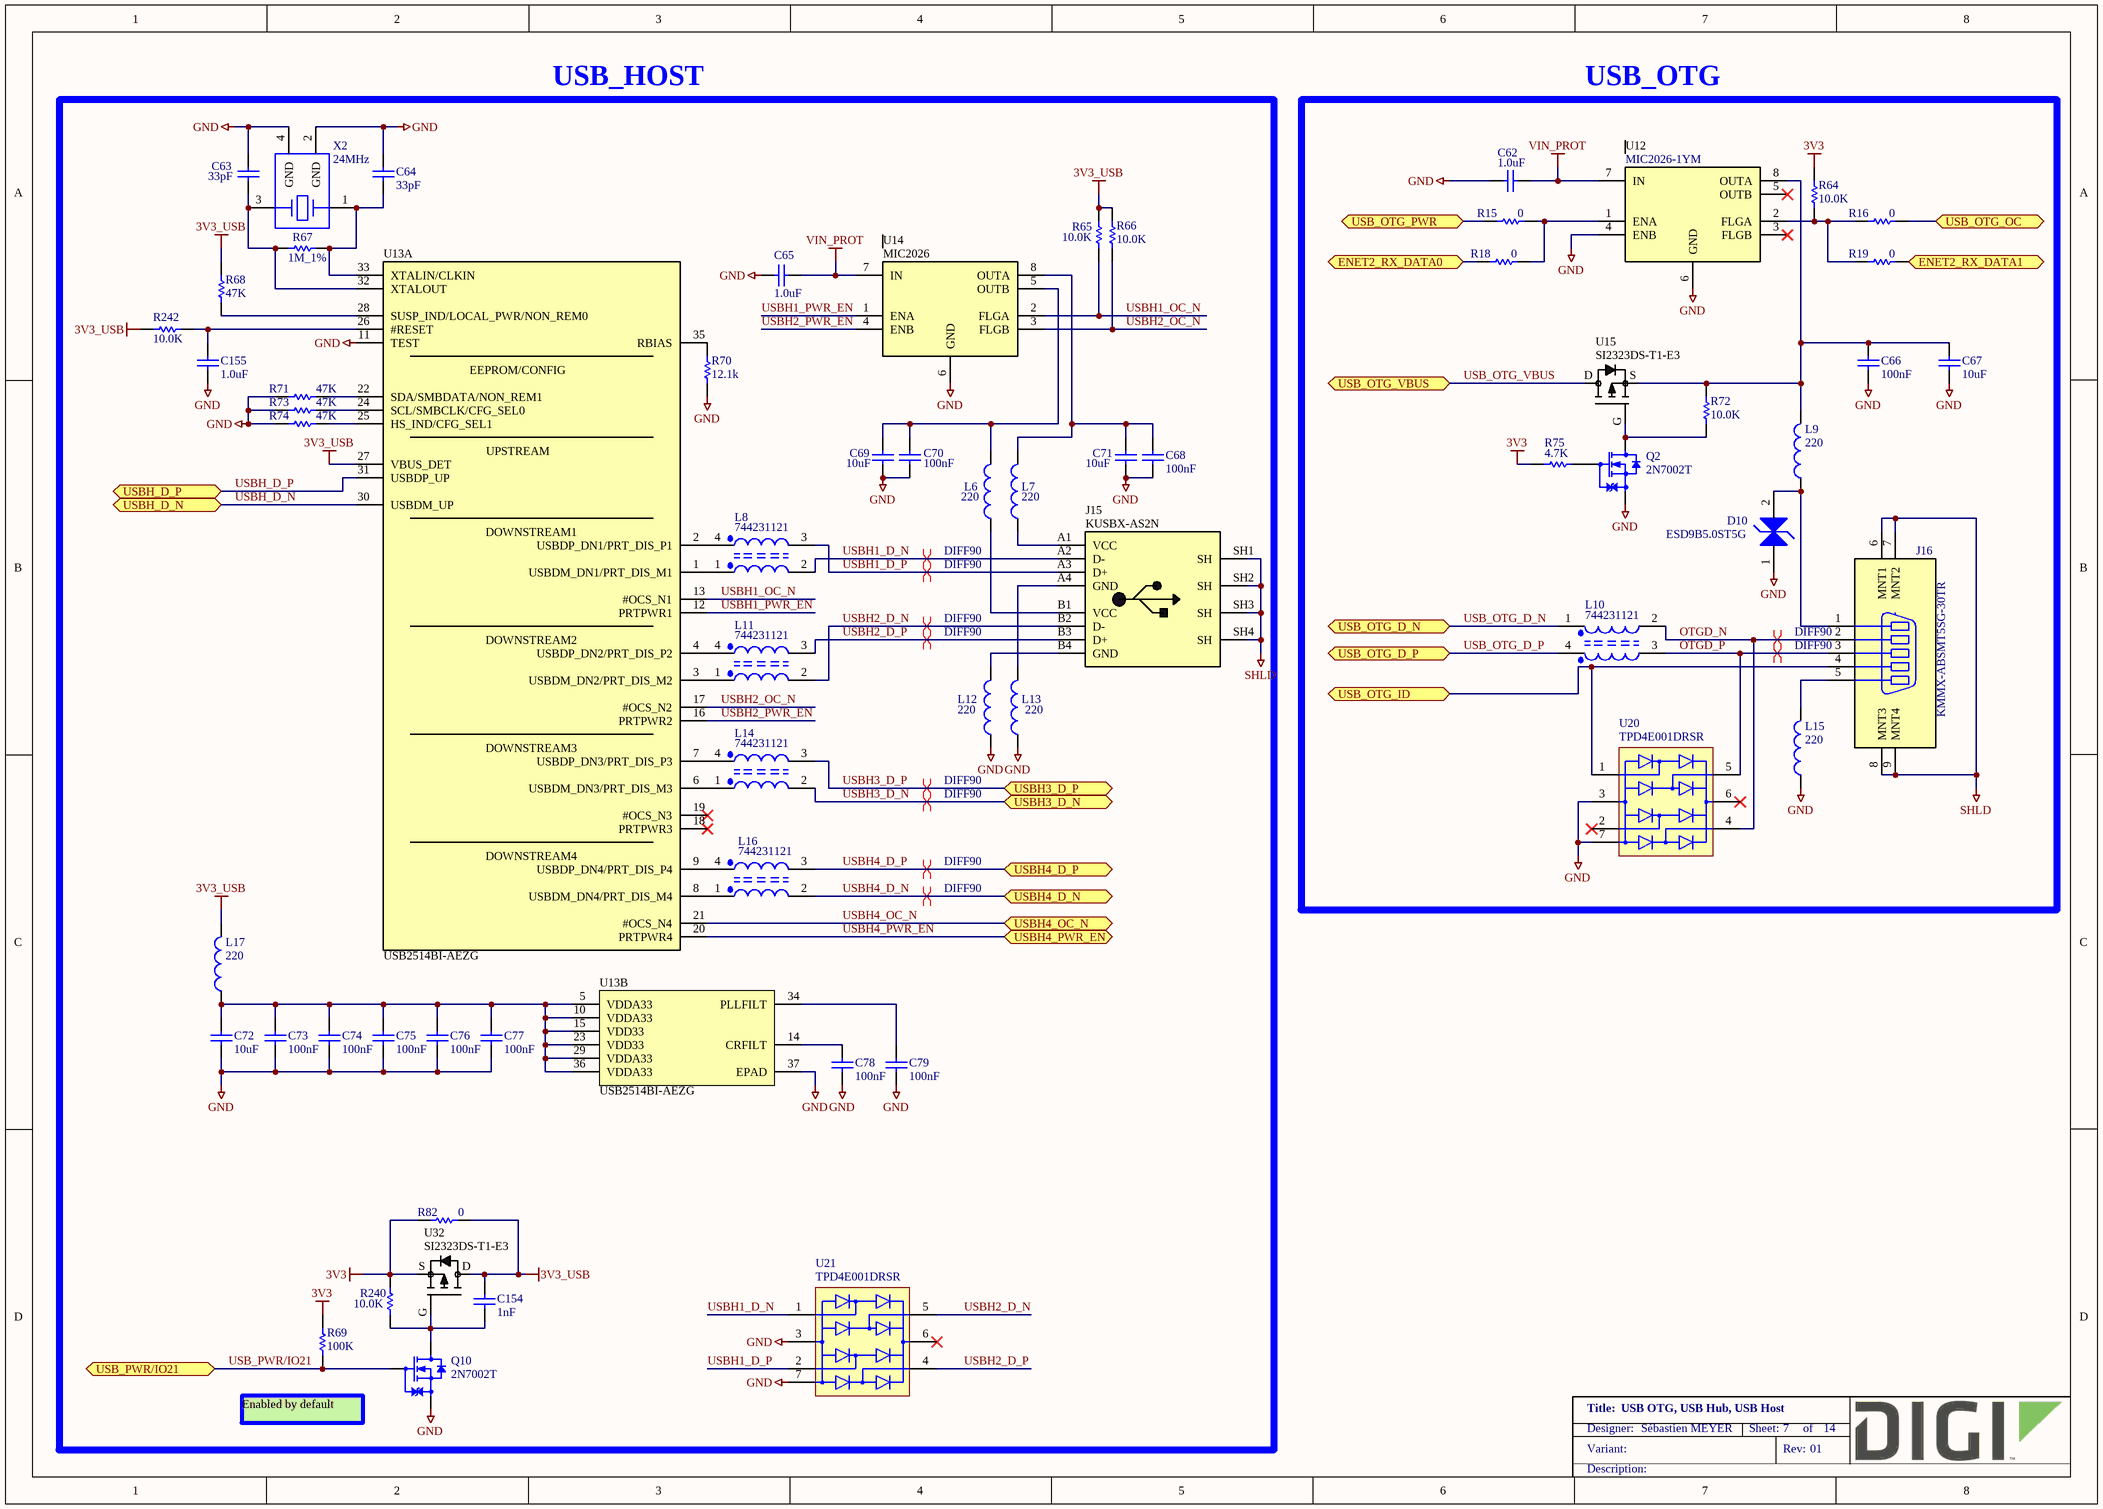
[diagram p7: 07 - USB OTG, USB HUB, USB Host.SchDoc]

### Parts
C62  1.0uF  [CAPC1005X55N]
C63  33pF  [CAPC1005X55N]
C64  33pF  [CAPC1005X55N]
C65  1.0uF  [CAPC1005X55N]
C66  100nF  [CAPC1005X55N]
C67  10uF  [CAPC1005X55N]
C68  100nF  [CAPC1005X55N]
C69  10uF  [CAPC1005X55N]
C70  100nF  [CAPC1005X55N]
C71  10uF  [CAPC1005X55N]
C72  10uF  [CAPC1005X55N]
C73  100nF  [CAPC1005X55N]
C74  100nF  [CAPC1005X55N]
C75  100nF  [CAPC1005X55N]
C76  100nF  [CAPC1005X55N]
C77  100nF  [CAPC1005X55N]
C78  100nF  [CAPC1005X55N]
C79  100nF  [CAPC1005X55N]
C154  1nF  [CAPC1005X55N]
C155  1.0uF  [CAPC1005X55N]
D10  ESD9B5.0ST5G  [SODFL1006X43N12]
J15  KUSBX-AS2N  [KYCON_KUSBX-AS2N]
J16  KMMX-ABSMT5SG-30TR  [KYCON_KMMX-ABSMT5]
L6  220  [INDC2013X110N]
L7  220  [INDC2013X110N]
L8  744231121  [FIL_DLW21H]
L9  220  [INDC2013X110N]
L10  744231121  [FIL_DLW21H]
L11  744231121  [FIL_DLW21H]
L12  220  [INDC2013X110N]
L13  220  [INDC2013X110N]
L14  744231121  [FIL_DLW21H]
L15  220  [INDC2013X110N]
L16  744231121  [FIL_DLW21H]
L17  220  [INDC2013X110N]
Q2  2N7002T  [SOTFL50P160X80_GSD-3N]
Q10  2N7002T  [SOTFL50P160X80_GSD-3N]
R15  0  [RESC1005X40N]
R16  0  [RESC1005X40N]
R18  0  [RESC1005X40N]
R19  0  [RESC1005X40N]
R64  10.0K  [RESC1005X40N]
R65  10.0K  [RESC1005X40N]
R66  10.0K  [RESC1005X40N]
R67  1M_1%  [RESC1005X40N]
R68  47K  [RESC1005X40N]
R69  100K  [RESC1005X40N]
R70  12.1k  [RESC1005X40N]
R71  47K  [RESC1005X40N]
R72  10.0K  [RESC1005X40N]
R73  47K  [RESC1005X40N]
R74  47K  [RESC1005X40N]
R75  4.7K  [RESC1005X40N]
R82  0  [RESC1609X55N]
R240  10.0K  [RESC1005X40N]
R242  10.0K  [RESC1005X40N]
U12  Manufacturer_Part_Number: MIC2026-1YM  [SOIC127P600X175-8N]  (hidden comment: MIC2026)
U13  USB2514BI-AEZG  [QFN50P600X600X100-37AN]  (parts A,B of 2)
U14  MIC2026  [SOIC127P600X175-8N]
U15  SI2323DS-T1-E3  [SOT95P240X110_GSD-3N]
U20  TPD4E001DRSR  [SON95P300X300X80-7N]
U21  TPD4E001DRSR  [SON95P300X300X80-7N]
U32  SI2323DS-T1-E3  [SOT95P240X110_GSD-3N]
X2  24MHz  [XTAL_C3E-3427]

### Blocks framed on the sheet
USB_HOST: C63-C65 C68-C79 C154 C155 J15 L6-L8 L11-L14 L16 L17 Q10 R65-R71 R73 R74 R82 R240 R242 U13 U14 U21 U32 X2
USB_OTG: C62 C66 C67 D10 J16 L9 L10 L15 Q2 R15 R16 R18 R19 R64 R72 R75 U12 U15 U20

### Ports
ENET2_RX_DATA0 (bidir), ENET2_RX_DATA1 (bidir), USB_OTG_D_N (bidir), USB_OTG_D_P (bidir), USB_OTG_ID (bidir), USB_OTG_OC (bidir), USB_OTG_PWR (bidir), USB_OTG_VBUS (bidir), USB_PWR/IO21 (bidir), USBH3_D_N (bidir), USBH3_D_P (bidir), USBH4_D_N (bidir), USBH4_D_P (bidir), USBH4_OC_N (bidir), USBH4_PWR_EN (bidir), USBH_D_N (bidir), USBH_D_P (bidir)

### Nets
3V3: R64.2 R69.1 R75.1 R82.1 R240.1 U32.S
3V3_USB: C154.2 L17.2 R65.2 R66.2 R68.2 R82.2 R242.1 U13.27(VBUS_DET) U32.D
GND: C62.1 C63.2 C64.2 C65.2 C66.1 C67.1 C68.1 C69.1 C70.1 C71.1 C72.1 C73.1 C74.1 C75.1 C76.1 C77.1 C78.1 C79.1 C155.1 D10.1 L12.1 L13.1 L15.1 Q2.S Q10.S R70.1 R71.1 R73.1 R74.1 U12.4(ENB) U12.6(GND) U13.11(TEST) U13.37(EPAD) U14.6(GND) U20.3(GND) U20.7(GND) U21.3(GND) U21.7(GND) X2.2(GND) X2.4(GND)
SHLD: J15.SH1(SH) J15.SH2(SH) J15.SH3(SH) J15.SH4(SH) J16.6(MNT1) J16.7(MNT2) J16.8(MNT3) J16.9(MNT4)
VIN_PROT: C62.2 C65.1 U12.7(IN) U14.7(IN)
ENET2_RX_DATA0: R18.1 ; port ENET2_RX_DATA0
ENET2_RX_DATA1: R19.2 ; port ENET2_RX_DATA1
OTGD_N: J16.2 L10.2 U20.4(I/O)
OTGD_P: J16.3 L10.3 U20.5(I/O)
USB_OTG_D_N: L10.1 ; port USB_OTG_D_N
USB_OTG_D_P: L10.4 ; port USB_OTG_D_P
USB_OTG_ID: J16.4 U20.1(I/O) ; port USB_OTG_ID
USB_OTG_OC: R16.2 ; port USB_OTG_OC
USB_OTG_PWR: R15.1 ; port USB_OTG_PWR
USB_OTG_VBUS: U15.D ; port USB_OTG_VBUS
USB_PWR/IO21: Q10.G R69.2 ; port USB_PWR/IO21
USBH1_D_N: J15.A2(D-) L8.2 U21.1(I/O)
USBH1_D_P: J15.A3(D+) L8.3 U21.2(I/O)
USBH1_OC_N: R65.1 U13.13(#OCS_N1) U14.2(FLGA)
USBH1_PWR_EN: U13.12(PRTPWR1) U14.1(ENA)
USBH2_D_N: J15.B2(D-) L11.2 U21.5(I/O)
USBH2_D_P: J15.B3(D+) L11.3 U21.4(I/O)
USBH2_OC_N: R66.1 U13.17(#OCS_N2) U14.3(FLGB)
USBH2_PWR_EN: U13.16(PRTPWR2) U14.4(ENB)
USBH3_D_N: L14.2 ; port USBH3_D_N
USBH3_D_P: L14.3 ; port USBH3_D_P
USBH4_D_N: L16.2 ; port USBH4_D_N
USBH4_D_P: L16.3 ; port USBH4_D_P
USBH4_OC_N: U13.21(#OCS_N4) ; port USBH4_OC_N
USBH4_PWR_EN: U13.20(PRTPWR4) ; port USBH4_PWR_EN
USBH_D_N: U13.30(USBDM_UP) ; port USBH_D_N
USBH_D_P: U13.31(USBDP_UP) ; port USBH_D_P
NetC63_1: C63.1 R67.1 U13.32(XTALOUT) X2.3
NetC64_1: C64.1 R67.2 U13.33(XTALIN/CLKIN) X2.1
NetC66_2: C66.2 C67.2 L9.2 R72.1 U12.8(OUTA) U15.S
NetC68_2: C68.2 C71.2 L7.2 U14.8(OUTA)
NetC69_2: C69.2 C70.2 L6.2 U14.5(OUTB)
NetC72_2: C72.2 C73.2 C74.2 C75.2 C76.2 C77.2 L17.1 U13.5(VDDA33) U13.10(VDDA33) U13.15(VDD33) U13.23(VDD33) U13.29(VDDA33) U13.36(VDDA33)
NetC78_2: C78.2 U13.14(CRFILT)
NetC79_2: C79.2 U13.34(PLLFILT)
NetC154_1: C154.1 Q10.D R240.2 U32.G
NetC155_2: C155.2 R242.2 U13.26(#RESET)
NetD10_2: D10.2 J16.1 L9.1
NetJ15_A1: J15.A1(VCC) L7.1
NetJ15_A4: J15.A4(GND) L13.2
NetJ15_B1: J15.B1(VCC) L6.1
NetJ15_B4: J15.B4(GND) L12.2
NetJ16_5: J16.5 L15.2
NetL8_1: L8.1 U13.1(USBDM_DN1/PRT_DIS_M1)
NetL8_4: L8.4 U13.2(USBDP_DN1/PRT_DIS_P1)
NetL11_1: L11.1 U13.3(USBDM_DN2/PRT_DIS_M2)
NetL11_4: L11.4 U13.4(USBDP_DN2/PRT_DIS_P2)
NetL14_1: L14.1 U13.6(USBDM_DN3/PRT_DIS_M3)
NetL14_4: L14.4 U13.7(USBDP_DN3/PRT_DIS_P3)
NetL16_1: L16.1 U13.8(USBDM_DN4/PRT_DIS_M4)
NetL16_4: L16.4 U13.9(USBDP_DN4/PRT_DIS_P4)
NetQ2_D: Q2.D R72.2 U15.G
NetQ2_G: Q2.G R75.2
NetR15_2: R15.2 R18.2 U12.1(ENA)
NetR16_1: R16.1 R19.1 R64.1 U12.2(FLGA)
NetR68_1: R68.1 U13.28(SUSP_IND/LOCAL_PWR/NON_REM0)
NetR70_2: R70.2 U13.35(RBIAS)
NetR71_2: R71.2 U13.22(SDA/SMBDATA/NON_REM1)
NetR73_2: R73.2 U13.24(SCL/SMBCLK/CFG_SEL0)
NetR74_2: R74.2 U13.25(HS_IND/CFG_SEL1)

Not connected (* = marked no-connect by the designer): U12 3(FLGB)* 5(OUTB)*; U13 18(PRTPWR3)* 19(#OCS_N3)*; U20 2(I/O)* 6(VCC)*; U21 6(VCC)*

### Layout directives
differential pair; net class DIFF90: OTGD_N, OTGD_P, USBH1_D_N, USBH1_D_P, USBH2_D_N, USBH2_D_P, USBH3_D_N, USBH3_D_P, USBH4_D_N, USBH4_D_P

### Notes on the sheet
- Enabled by default

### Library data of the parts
C62 C65 C155 = 1001167: as C18 on sheet 06 - Ethernet
C63 C64 = 1000010: CAP 33pF 50V 5% NP0 0402; Part_Type: Capacitor; Manufacturer: Murata; Manufacturer_Part_Number: GRM1555C1H330JA01D; Component_Life_Cycle_State: Proven; Area: 0.95; Project: USB UART to USB Transceiver; Tolerance: 5; Digi_PN: 14050738
C66 C68 C70 C73-C79 = 1000006: as C20 on sheet 05 - JTAG, SWD, Console, UART, IO expander
C67 C69 C71 C72 = 1001168: CAP CER 10UF 10V 20% X5R 0402; Part_Type: Capacitor; Manufacturer: Samsung; Manufacturer_Part_Number: CL05A106MP5NUNC; Digi_PN: 14050689; Component_Life_Cycle_State: Reviewed; Area: 0.95; Project: CCWMX6_SBC board
C154 = 1000067: as C26 on sheet 06 - Ethernet
D10 = 1001264: TVS DIODE 5VWM SOD923; Part_Type: Diodes; Manufacturer: On Semiconductor; Digi_PN: 17050587; Component_Life_Cycle_State: Reviewed; Area: 1.5; Project: CCWMX6_SBC board
J15 = 1001121: USB Stacked Dual A type; Part_Type: Connector; Manufacturer: KYCON; Digi_PN: 18000276; Component_Life_Cycle_State: Reviewed; Area: 164; Project: CCWMX6_SBC board
J16 = 1001117: CONN RECEPT MICRO-USB TYPE AB R/A; Part_Type: Connector; Manufacturer: KYCON; Digi_PN: 18000401; Component_Life_Cycle_State: Reviewed; Area: 40; Project: CCWMX6_SBC board
L6 L7 L9 L12 L13 L15 L17 = 1001174: as L2 on sheet 06 - Ethernet
L8 L10 L11 L14 L16 = 1001173: CHOKE COM MODE 120 OHM .37A; Part_Type: Inductor; Manufacturer: Wurth Electronics Inc; Digi_PN: 21000143; Component_Life_Cycle_State: Reviewed; Area: 2.4; Project: CCWMX6_SBC board
Q2 Q10 = 1000715: as Q7 on sheet 06 - Ethernet
R15 R16 R18 R19 = 1000076: as R81 on sheet 05 - JTAG, SWD, Console, UART, IO expander
R64-R66 R72 R240 R242 = 1000537: as R36 on sheet 05 - JTAG, SWD, Console, UART, IO expander
R67 = 1000971: RES 1.00M OHM 1/16W 1% 0402 SMD; Part_Type: Resistor; Manufacturer: Yageo; Manufacturer_Part_Number: RC0402FR-071ML; Digi_PN: 13050561; Component_Life_Cycle_State: Reviewed; Area: 0.95; Project: ConnectCore i.MX6 module; Power_WV_SRF: 63; Tolerance: 1; Note: 13051098 = Digi No. for GE WDNU
R68 R71 R73 R74 = 1001155: RES 47.0K OHM 1/16W 1% 0402 SMD; Part_Type: Resistor; Manufacturer: Vishay Dale; Manufacturer_Part_Number: CRCW040247K0FKED; Digi_PN: 13050646; Component_Life_Cycle_State: Reviewed; Area: 0.95; Project: CCWMX6_SBC board
R69 = 1000480: as R51 on sheet 06 - Ethernet
R70 = 1000828: as R54 on sheet 06 - Ethernet
R75 = 1000038: as R37 on sheet 05 - JTAG, SWD, Console, UART, IO expander
R82 = 1000208: as R27 on sheet 06 - Ethernet
U12 = 1001143: IC SW DISTRIBUTION 2CHAN 8SOIC; Manufacturer: Micrel; Digi_PN: 16051879; Component_Life_Cycle_State: Reviewed; Area: 29.58; Project: CCWMX6_SBC board
U13 = 1001114: 4-PORT USB 2.0 HUB CTRLR 36VQFN; Part_Type: IC; Manufacturer: SMSC; Digi_PN: 16051280; Component_Life_Cycle_State: Reviewed; Area: 36; Project: CCWMX6_SBC board
U14 = 1001143: IC SW DISTRIBUTION 2CHAN 8SOIC; Manufacturer: Micrel; Manufacturer_Part_Number: MIC2026-1YM; Digi_PN: 16051879; Component_Life_Cycle_State: Reviewed; Area: 29.58; Project: CCWMX6_SBC board
U15 U32 = 1001163: as U8 on sheet 06 - Ethernet
U20 U21 = 1001265: TVS DIODE 5.5VWM 6SON; Part_Type: IC; Manufacturer: Texas Instruments; Digi_PN: 17050690; Component_Life_Cycle_State: Reviewed; Area: 10; Project: CCWMX6_SBC board; Note: 17050839 = Digi No. for GE WDNU
X2 = 1001134: CRYSTAL 24MHZ 18PF SMD; Part_Type: Crystals-Oscillators; Manufacturer: Aker; Manufacturer_Part_Number: C3E-24.000-18-3030-X-R; Digi_PN: 20000223; Component_Life_Cycle_State: Reviewed; Area: 9.18; Project: CCWMX6_SBC board

## Sheet 08 - Displays and camera.SchDoc: Displays and Cameras
size A3; PageSetup: Record=PageOptions¦CenterHorizontal=True¦CenterVertical=True¦PrintScale=0.70¦XCorrection=1.00¦YCorrection=1.00¦PrintKind=0¦BorderSize=5000000¦LeftOffset=0¦BottomOffset=0¦Orientation=2¦PaperLength=4200¦PaperWidth=2970¦Scale=100¦PaperSource=7¦PrintQuality=600¦MediaType=1¦DitherType=10¦PaperKind=A4¦PrintScaleMode=1; Author: Sébastien MEYER; SheetNumber: 8; SheetTotal: 14
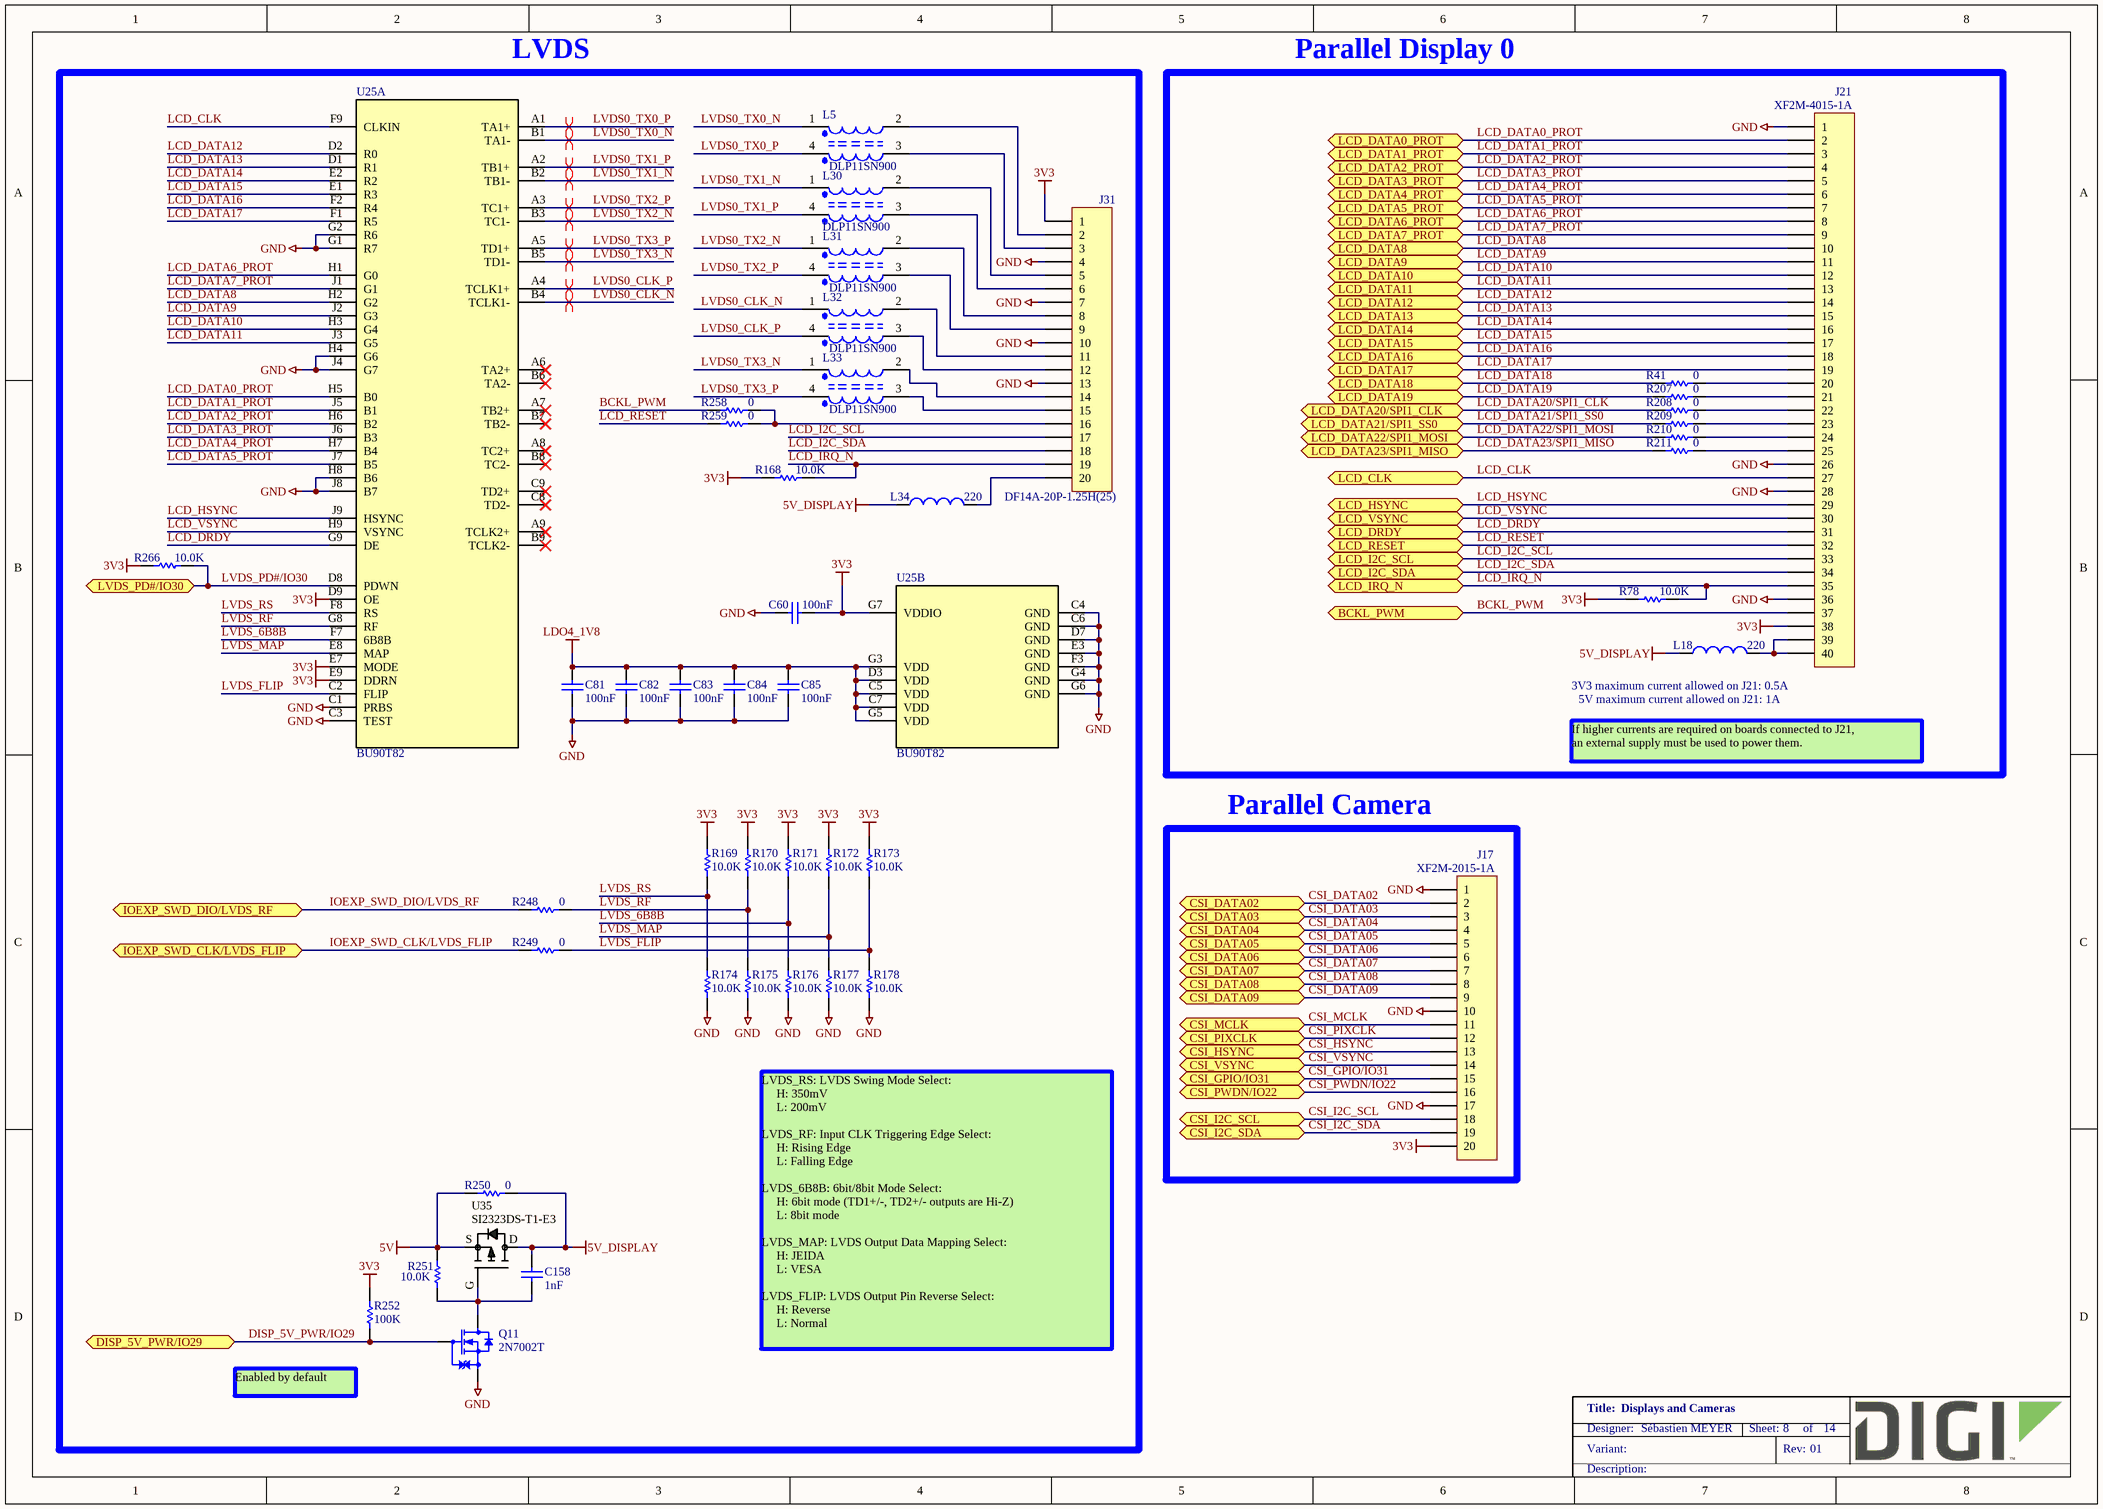
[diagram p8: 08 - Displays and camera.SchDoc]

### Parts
C60  100nF  [CAPC1005X55N]
C81  100nF  [CAPC1005X55N]
C82  100nF  [CAPC1005X55N]
C83  100nF  [CAPC1005X55N]
C84  100nF  [CAPC1005X55N]
C85  100nF  [CAPC1005X55N]
C158  1nF  [CAPC1005X55N]
J17  Manufacturer_Part_Number: XF2M-2015-1A  [omron_xf2m-2015-1a]  (hidden comment: 1x20P)
J21  Manufacturer_Part_Number: XF2M-4015-1A  [OMRON_XF2M-4015-1A]  (hidden comment: 1x40)
J31  DF14A-20P-1.25H(25)  [HIROSE_DF14A-20P-1.25H]
L5  DLP11SN900  [FIL_DLP11S]
L18  220  [INDC2013X110N]
L30  DLP11SN900  [FIL_DLP11S]
L31  DLP11SN900  [FIL_DLP11S]
L32  DLP11SN900  [FIL_DLP11S]
L33  DLP11SN900  [FIL_DLP11S]
L34  220  [INDC2013X110N]
Q11  2N7002T  [SOTFL50P160X80_GSD-3N]
R41  0  [RESC1005X40N]
R78  10.0K  [RESC1005X40N]
R168  10.0K  [RESC1005X40N]
R169  10.0K  [RESC1005X40N]
R170  10.0K  [RESC1005X40N]
R171  10.0K  [RESC1005X40N]
R172  10.0K  [RESC1005X40N]
R173  10.0K  [RESC1005X40N]
R174  10.0K  [RESC1005X40N]
R175  10.0K  [RESC1005X40N]
R176  10.0K  [RESC1005X40N]
R177  10.0K  [RESC1005X40N]
R178  10.0K  [RESC1005X40N]
R207  0  [RESC1005X40N]
R208  0  [RESC1005X40N]
R209  0  [RESC1005X40N]
R210  0  [RESC1005X40N]
R211  0  [RESC1005X40N]
R248  0  [RESC1005X40N]
R249  0  [RESC1005X40N]
R250  0  [RESC1609X55N]
R251  10.0K  [RESC1005X40N]
R252  100K  [RESC1005X40N]
R258  0  [RESC1005X40N]
R259  0  [RESC1005X40N]
R266  10.0K  [RESC1005X40N]
U25  BU90T82  [BGA72C65P9X9_700X700X112]  (parts A,B of 2)
U35  SI2323DS-T1-E3  [SOT95P240X110_GSD-3N]

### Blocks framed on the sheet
LVDS: C60 C81-C85 C158 J31 L5 L30-L34 Q11 R168-R178 R248-R252 R258 R259 R266 U25 U35
Parallel Display 0: J21 L18 R41 R78 R207-R211
Parallel Camera: J17

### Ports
BCKL_PWM (bidir), CSI_DATA02 (bidir), CSI_DATA03 (bidir), CSI_DATA04 (bidir), CSI_DATA05 (bidir), CSI_DATA06 (bidir), CSI_DATA07 (bidir), CSI_DATA08 (bidir), CSI_DATA09 (bidir), CSI_GPIO/IO31 (bidir), CSI_HSYNC (bidir), CSI_I2C_SCL (bidir), CSI_I2C_SDA (bidir), CSI_MCLK (bidir), CSI_PIXCLK (bidir), CSI_PWDN/IO22 (bidir), CSI_VSYNC (bidir), DISP_5V_PWR/IO29 (bidir), IOEXP_SWD_CLK/LVDS_FLIP (bidir), IOEXP_SWD_DIO/LVDS_RF (bidir), LCD_CLK (bidir), LCD_DATA0_PROT (bidir), LCD_DATA1_PROT (bidir), LCD_DATA2_PROT (bidir), LCD_DATA3_PROT (bidir), LCD_DATA4_PROT (bidir), LCD_DATA5_PROT (bidir), LCD_DATA6_PROT (bidir), LCD_DATA7_PROT (bidir), LCD_DATA8 (bidir), LCD_DATA9 (bidir), LCD_DATA10 (bidir), LCD_DATA11 (bidir), LCD_DATA12 (bidir), LCD_DATA13 (bidir), LCD_DATA14 (bidir), LCD_DATA15 (bidir), LCD_DATA16 (bidir), LCD_DATA17 (bidir), LCD_DATA18 (bidir), LCD_DATA19 (bidir), LCD_DATA20/SPI1_CLK (bidir), LCD_DATA21/SPI1_SS0 (bidir), LCD_DATA22/SPI1_MOSI (bidir), LCD_DATA23/SPI1_MISO (bidir), LCD_DRDY (bidir), LCD_HSYNC (bidir), LCD_I2C_SCL (bidir), LCD_I2C_SDA (bidir), LCD_IRQ_N (bidir), LCD_RESET (bidir), LCD_VSYNC (bidir), LVDS_PD#/IO30 (bidir)

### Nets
3V3: C60.1 J17.20 J21.38 J31.1 R78.1 R168.1 R169.2 R170.2 R171.2 R172.2 R173.2 R252.1 R266.1 U25.D9(OE) U25.E7(MODE) U25.E9(DDRN) U25.G7(VDDIO)
5V: R250.1 R251.1 U35.S
5V_DISPLAY: C158.2 L18.1 L34.1 R250.2 U35.D
GND: C60.2 C81.2 C82.2 C83.2 C84.2 C85.2 J17.1 J17.10 J17.17 J21.1 J21.26 J21.28 J21.36 J31.4 J31.7 J31.10 J31.13 Q11.S R174.1 R175.1 R176.1 R177.1 R178.1 U25.C1(PRBS) U25.C3(TEST) U25.C4(GND) U25.C6(GND) U25.D7(GND) U25.E3(GND) U25.F3(GND) U25.G1(R7) U25.G2(R6) U25.G4(GND) U25.G6(GND) U25.H4(G6) U25.H8(B6) U25.J4(G7) U25.J8(B7)
LDO4_1V8: C81.1 C82.1 C83.1 C84.1 C85.1 U25.C5(VDD) U25.C7(VDD) U25.D3(VDD) U25.G3(VDD) U25.G5(VDD)
BCKL_PWM: J21.37 R258.1 ; port BCKL_PWM
CSI_DATA02: J17.2 ; port CSI_DATA02
CSI_DATA03: J17.3 ; port CSI_DATA03
CSI_DATA04: J17.4 ; port CSI_DATA04
CSI_DATA05: J17.5 ; port CSI_DATA05
CSI_DATA06: J17.6 ; port CSI_DATA06
CSI_DATA07: J17.7 ; port CSI_DATA07
CSI_DATA08: J17.8 ; port CSI_DATA08
CSI_DATA09: J17.9 ; port CSI_DATA09
CSI_GPIO/IO31: J17.15 ; port CSI_GPIO/IO31
CSI_HSYNC: J17.13 ; port CSI_HSYNC
CSI_I2C_SCL: J17.18 ; port CSI_I2C_SCL
CSI_I2C_SDA: J17.19 ; port CSI_I2C_SDA
CSI_MCLK: J17.11 ; port CSI_MCLK
CSI_PIXCLK: J17.12 ; port CSI_PIXCLK
CSI_PWDN/IO22: J17.16 ; port CSI_PWDN/IO22
CSI_VSYNC: J17.14 ; port CSI_VSYNC
DISP_5V_PWR/IO29: Q11.G R252.2 ; port DISP_5V_PWR/IO29
IOEXP_SWD_CLK/LVDS_FLIP: R249.1 ; port IOEXP_SWD_CLK/LVDS_FLIP
IOEXP_SWD_DIO/LVDS_RF: R248.1 ; port IOEXP_SWD_DIO/LVDS_RF
LCD_CLK: J21.27 U25.F9(CLKIN) ; port LCD_CLK
LCD_DATA0_PROT: J21.2 U25.H5(B0) ; port LCD_DATA0_PROT
LCD_DATA1_PROT: J21.3 U25.J5(B1) ; port LCD_DATA1_PROT
LCD_DATA2_PROT: J21.4 U25.H6(B2) ; port LCD_DATA2_PROT
LCD_DATA3_PROT: J21.5 U25.J6(B3) ; port LCD_DATA3_PROT
LCD_DATA4_PROT: J21.6 U25.H7(B4) ; port LCD_DATA4_PROT
LCD_DATA5_PROT: J21.7 U25.J7(B5) ; port LCD_DATA5_PROT
LCD_DATA6_PROT: J21.8 U25.H1(G0) ; port LCD_DATA6_PROT
LCD_DATA7_PROT: J21.9 U25.J1(G1) ; port LCD_DATA7_PROT
LCD_DATA8: J21.10 U25.H2(G2) ; port LCD_DATA8
LCD_DATA9: J21.11 U25.J2(G3) ; port LCD_DATA9
LCD_DATA10: J21.12 U25.H3(G4) ; port LCD_DATA10
LCD_DATA11: J21.13 U25.J3(G5) ; port LCD_DATA11
LCD_DATA12: J21.14 U25.D2(R0) ; port LCD_DATA12
LCD_DATA13: J21.15 U25.D1(R1) ; port LCD_DATA13
LCD_DATA14: J21.16 U25.E2(R2) ; port LCD_DATA14
LCD_DATA15: J21.17 U25.E1(R3) ; port LCD_DATA15
LCD_DATA16: J21.18 U25.F2(R4) ; port LCD_DATA16
LCD_DATA17: J21.19 U25.F1(R5) ; port LCD_DATA17
LCD_DATA18: R41.1 ; port LCD_DATA18
LCD_DATA19: R207.1 ; port LCD_DATA19
LCD_DATA20/SPI1_CLK: R208.1 ; port LCD_DATA20/SPI1_CLK
LCD_DATA21/SPI1_SS0: R209.1 ; port LCD_DATA21/SPI1_SS0
LCD_DATA22/SPI1_MOSI: R210.1 ; port LCD_DATA22/SPI1_MOSI
LCD_DATA23/SPI1_MISO: R211.1 ; port LCD_DATA23/SPI1_MISO
LCD_DRDY: J21.31 U25.G9(DE) ; port LCD_DRDY
LCD_HSYNC: J21.29 U25.J9(HSYNC) ; port LCD_HSYNC
LCD_I2C_SCL: J21.33 J31.17 ; port LCD_I2C_SCL
LCD_I2C_SDA: J21.34 J31.18 ; port LCD_I2C_SDA
LCD_IRQ_N: J21.35 J31.19 R78.2 R168.2 ; port LCD_IRQ_N
LCD_RESET: J21.32 R259.1 ; port LCD_RESET
LCD_VSYNC: J21.30 U25.H9(VSYNC) ; port LCD_VSYNC
LVDS0_CLK_N: L32.1 U25.B4(TCLK1-)
LVDS0_CLK_P: L32.4 U25.A4(TCLK1+)
LVDS0_TX0_N: L5.1 U25.B1(TA1-)
LVDS0_TX0_P: L5.4 U25.A1(TA1+)
LVDS0_TX1_N: L30.1 U25.B2(TB1-)
LVDS0_TX1_P: L30.4 U25.A2(TB1+)
LVDS0_TX2_N: L31.1 U25.B3(TC1-)
LVDS0_TX2_P: L31.4 U25.A3(TC1+)
LVDS0_TX3_N: L33.1 U25.B5(TD1-)
LVDS0_TX3_P: L33.4 U25.A5(TD1+)
LVDS_6B8B: R171.1 R176.2 U25.F7(6B8B)
LVDS_FLIP: R173.1 R178.2 R249.2 U25.C2(FLIP)
LVDS_MAP: R172.1 R177.2 U25.E8(MAP)
LVDS_PD#/IO30: R266.2 U25.D8(PDWN) ; port LVDS_PD#/IO30
LVDS_RF: R170.1 R175.2 R248.2 U25.G8(RF)
LVDS_RS: R169.1 R174.2 U25.F8(RS)
NetC158_1: C158.1 Q11.D R251.2 U35.G
NetJ21_20: J21.20 R41.2
NetJ21_21: J21.21 R207.2
NetJ21_22: J21.22 R208.2
NetJ21_23: J21.23 R209.2
NetJ21_24: J21.24 R210.2
NetJ21_25: J21.25 R211.2
NetJ21_39: J21.39 J21.40 L18.2
NetJ31_2: J31.2 L5.2
NetJ31_3: J31.3 L5.3
NetJ31_5: J31.5 L30.2
NetJ31_6: J31.6 L30.3
NetJ31_8: J31.8 L31.2
NetJ31_9: J31.9 L31.3
NetJ31_11: J31.11 L32.2
NetJ31_12: J31.12 L32.3
NetJ31_14: J31.14 L33.2
NetJ31_15: J31.15 L33.3
NetJ31_16: J31.16 R258.2 R259.2
NetJ31_20: J31.20 L34.2

Not connected (* = marked no-connect by the designer): U25 A6(TA2+)* A7(TB2+)* A8(TC2+)* A9(TCLK2+)* B6(TA2-)* B7(TB2-)* B8(TC2-)* B9(TCLK2-)* C8(TD2-)* C9(TD2+)*

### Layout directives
differential pair: LVDS0_CLK_N, LVDS0_CLK_P, LVDS0_TX0_N, LVDS0_TX0_P, LVDS0_TX1_N, LVDS0_TX1_P, LVDS0_TX2_N, LVDS0_TX2_P, LVDS0_TX3_N, LVDS0_TX3_P

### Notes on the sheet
- 3V3 maximum current allowed on J21: 0.5A
- 5V maximum current allowed on J21: 1A
- If higher currents are required on boards connected to J21,
  an external supply must be used to power them.
- (near R252) Enabled by default
- LVDS_RS: LVDS Swing Mode Select:
  H: 350mV
  L: 200mV
  LVDS_RF: Input CLK Triggering Edge Select:
  H: Rising Edge
  L: Falling Edge
  LVDS_6B8B: 6bit/8bit Mode Select:
  H: 6bit mode (TD1+/-, TD2+/- outputs are Hi-Z)
  L: 8bit mode
  LVDS_MAP: LVDS Output Data Mapping Select:
  H: JEIDA
  L: VESA
  LVDS_FLIP: LVDS Output Pin Reverse Select:
  H: Reverse
  L: Normal

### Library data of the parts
C60 C81-C85 = 1000006: as C20 on sheet 05 - JTAG, SWD, Console, UART, IO expander
C158 = 1000067: as C26 on sheet 06 - Ethernet
J17 = 1001145: CONN FPC 20POS 0.5MM PITCH SMD; Part_Type: Connector; Manufacturer: Omron; Digi_PN: 18000675; Component_Life_Cycle_State: Reviewed; Area: 69.09; Project: CCWMX6_SBC board
J21 = 1001144: CONN FPC 40POS 0.5MM PITCH SMD; Part_Type: Connector; Manufacturer: Omron; Digi_PN: 18000676; Component_Life_Cycle_State: Reviewed; Area: 117.5; Project: CCWMX6_SBC board
J31 = 1001132: CONN HEADER 20POS 1.25MM R/A SMD; Part_Type: Connector; Manufacturer: Hirose; Digi_PN: 18050231; Component_Life_Cycle_State: Reviewed; Area: 206.34; Project: CCWMX6_SBC board
L5 L30-L33 = 1001014: CHOKE COIL COMMON MODE 150MA SMD; Part_Type: Inductor; Manufacturer: Murata; Manufacturer_Part_Number: DLP11SN900HL2L; Component_Life_Cycle_State: Reviewed; Area: 3.94; Project: ResMed RF Test Interface Board; Digi_PN: 21000531
L18 L34 = 1001174: as L2 on sheet 06 - Ethernet
Q11 = 1000715: as Q7 on sheet 06 - Ethernet
R41 R207-R211 R248 R249 R258 R259 = 1000076: as R81 on sheet 05 - JTAG, SWD, Console, UART, IO expander
R78 R168-R178 R251 R266 = 1000537: as R36 on sheet 05 - JTAG, SWD, Console, UART, IO expander
R250 = 1000208: as R27 on sheet 06 - Ethernet
R252 = 1000480: as R51 on sheet 06 - Ethernet
U25 = 1001994: SMIC, 27-bit LVDS dual-out transmitter; Part_Type: IC; Manufacturer: Rohm; Manufacturer_Part_Number: BU90T82-ZE2; Component_Life_Cycle_State: Reviewed; Area: 64; Project: iMX6UL+PMIC; Digi_PN: 16052031
U35 = 1001163: as U8 on sheet 06 - Ethernet

## Sheet 09 - Audio.SchDoc: Audio
size A3; PageSetup: Record=PageOptions¦CenterHorizontal=True¦CenterVertical=True¦PrintScale=0.70¦XCorrection=1.00¦YCorrection=1.00¦PrintKind=0¦BorderSize=5000000¦LeftOffset=0¦BottomOffset=0¦Orientation=2¦PaperLength=4200¦PaperWidth=2970¦Scale=100¦PaperSource=7¦PrintQuality=600¦MediaType=1¦DitherType=10¦PaperKind=A4¦PrintScaleMode=1; Author: Sébastien MEYER; SheetNumber: 9; SheetTotal: 14
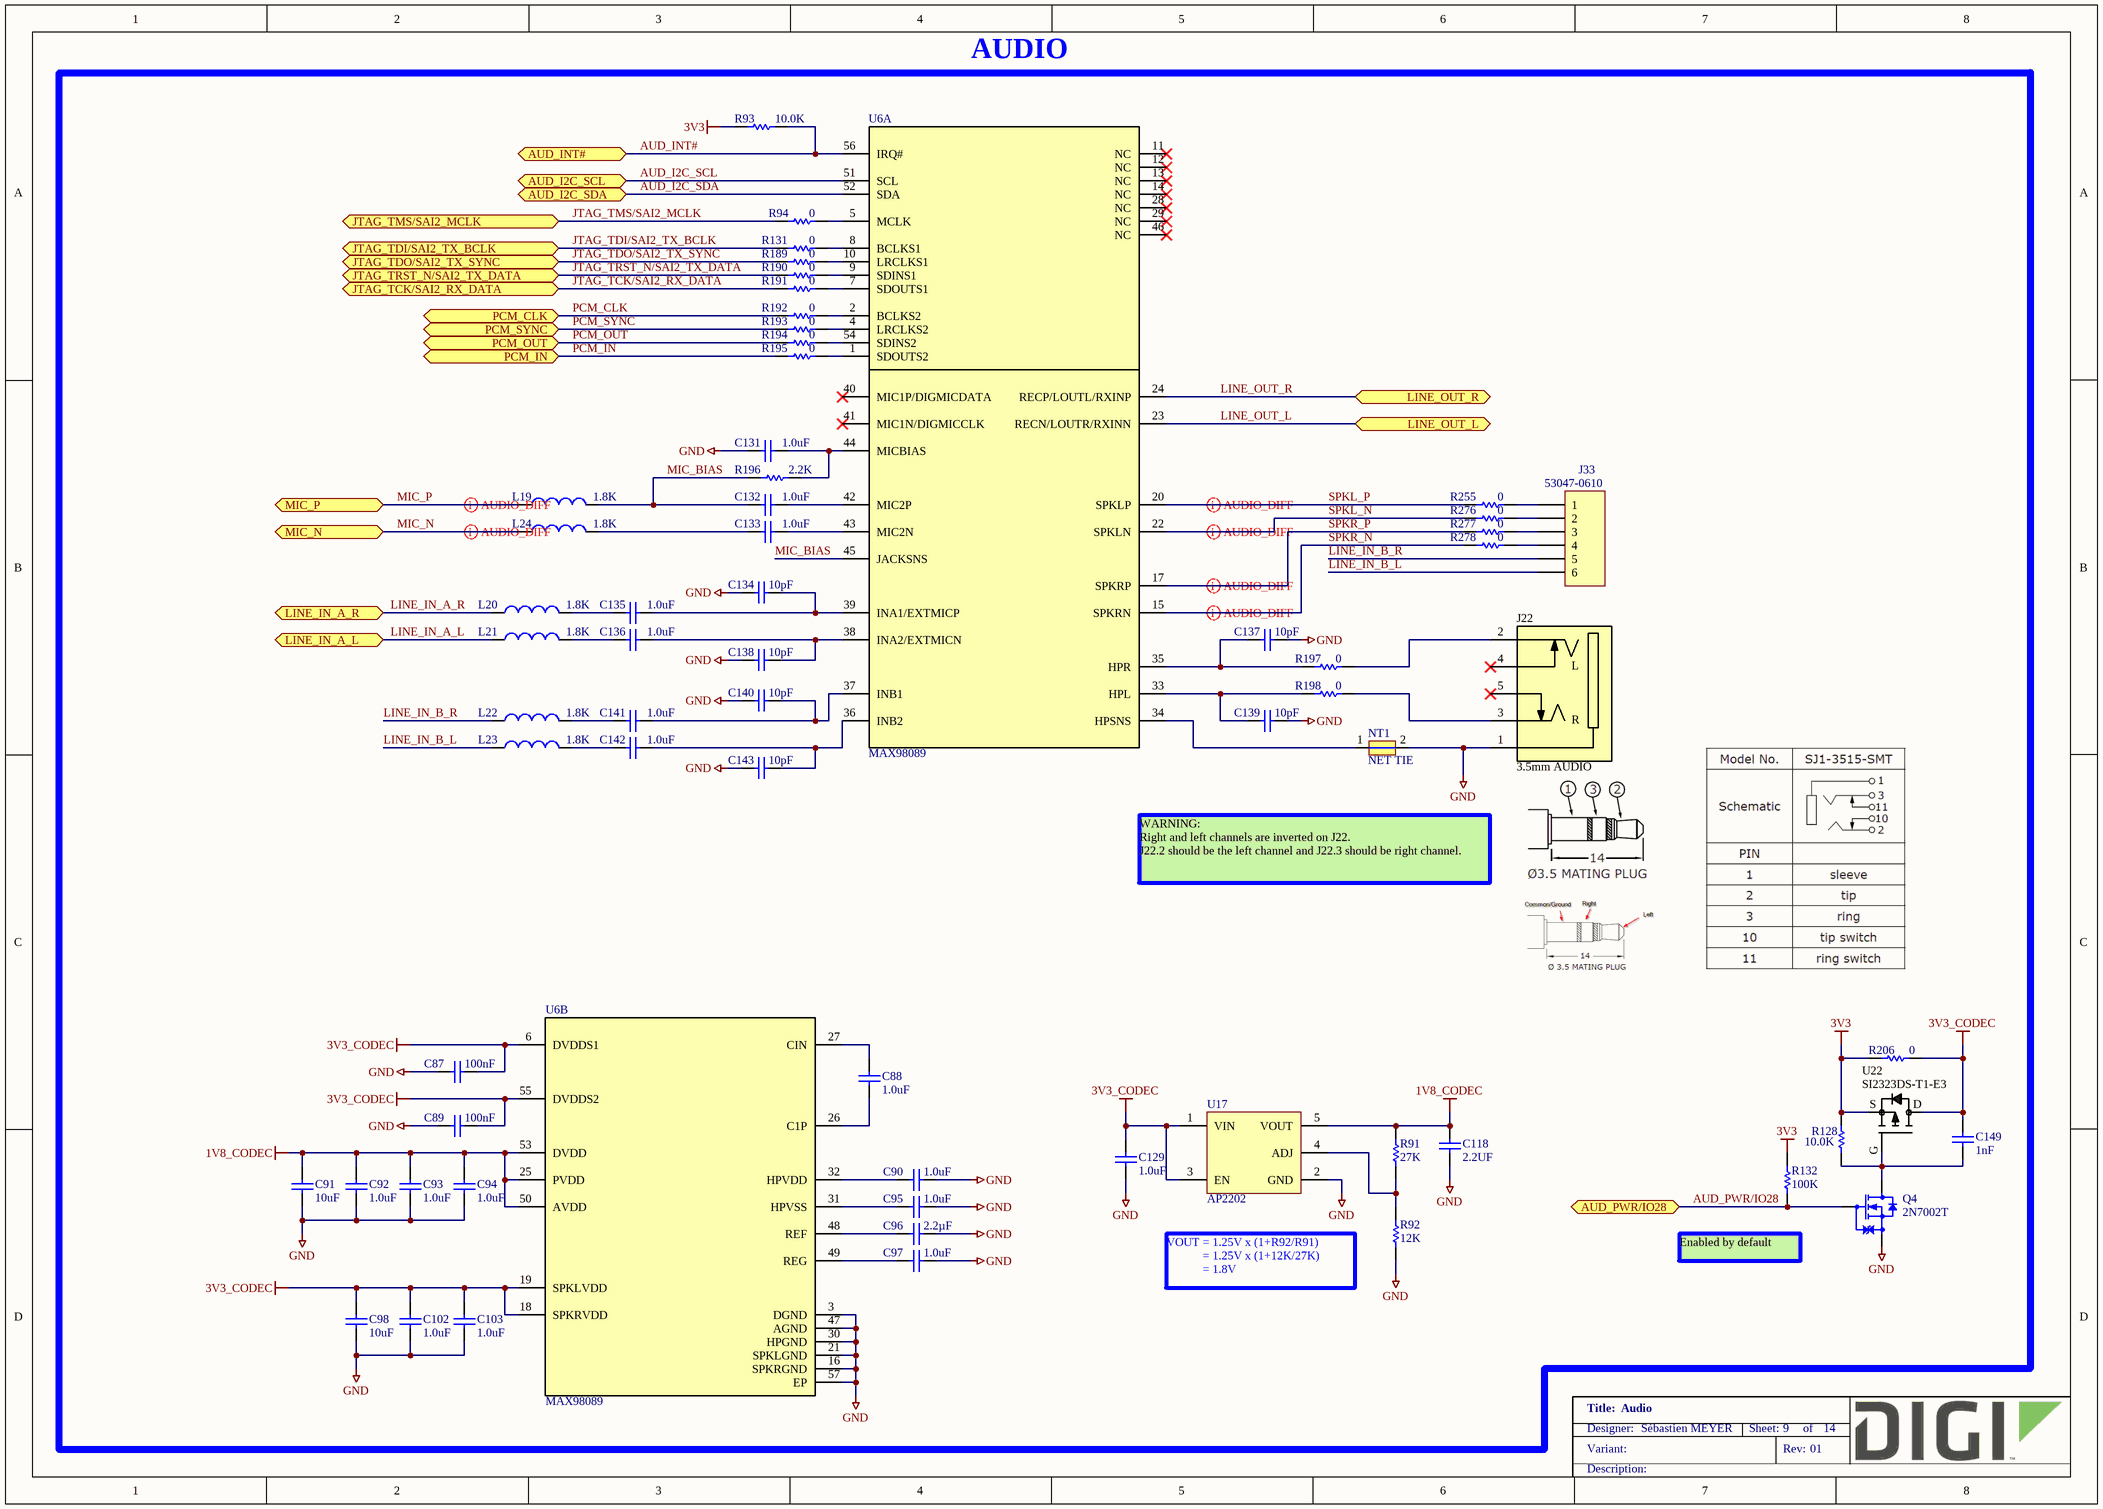
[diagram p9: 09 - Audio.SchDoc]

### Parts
C87  100nF  [CAPC1005X55N]
C88  1.0uF  [CAPC1005X55N]
C89  100nF  [CAPC1005X55N]
C90  1.0uF  [CAPC1005X55N]
C91  10uF  [CAPC2013X135N]
C92  1.0uF  [CAPC1005X55N]
C93  1.0uF  [CAPC1005X55N]
C94  1.0uF  [CAPC1005X55N]
C95  1.0uF  [CAPC1005X55N]
C96  2.2µF  [CAPC1005X55N]
C97  1.0uF  [CAPC1005X55N]
C98  10uF  [CAPC2013X135N]
C102  1.0uF  [CAPC1005X55N]
C103  1.0uF  [CAPC1005X55N]
C118  2.2UF  [CAPC1608X90N]
C129  1.0uF  [CAPC1005X55L]
C131  1.0uF  [CAPC1005X55L]
C132  1.0uF  [CAPC1005X55L]
C133  1.0uF  [CAPC1005X55L]
C134  10pF  [CAPC1005X55N]
C135  1.0uF  [CAPC1005X55L]
C136  1.0uF  [CAPC1005X55L]
C137  10pF  [CAPC1005X55N]
C138  10pF  [CAPC1005X55N]
C139  10pF  [CAPC1005X55N]
C140  10pF  [CAPC1005X55N]
C141  1.0uF  [CAPC1005X55L]
C142  1.0uF  [CAPC1005X55L]
C143  10pF  [CAPC1005X55N]
C149  1nF  [CAPC1005X55N]
J22  3.5mm AUDIO  [CUI_SJ1-3515-SMT]
J33  Manufacturer_Part_Number: 53047-0610  [MOLEX_53047-0610]  (hidden comment: 1x6P)
L19  1.8K  [INDC1005X60N]
L20  1.8K  [INDC1005X60N]
L21  1.8K  [INDC1005X60N]
L22  1.8K  [INDC1005X60N]
L23  1.8K  [INDC1005X60N]
L24  1.8K  [INDC1005X60N]
NT1  NET TIE  [NET_TIE_4mil]  (net tie, no BOM)
Q4  2N7002T  [SOTFL50P160X80_GSD-3N]
R91  27K  [RESC1005X40N]
R92  12K  [RESC1609X55N]
R93  10.0K  [RESC1005X40N]
R94  0  [RESC1005X40N]
R128  10.0K  [RESC1005X40N]
R131  0  [RESC1005X40N]
R132  100K  [RESC1005X40N]
R189  0  [RESC1005X40N]
R190  0  [RESC1005X40N]
R191  0  [RESC1005X40N]
R192  0  [RESC1005X40N]
R193  0  [RESC1005X40N]
R194  0  [RESC1005X40N]
R195  0  [RESC1005X40N]
R196  2.2K  [RESC1005X40N]
R197  0  [RESC1005X40N]
R198  0  [RESC1005X40N]
R206  0  [RESC1609X55N]
R255  0  [RESC1005X40N]
R276  0  [RESC1005X40N]
R277  0  [RESC1005X40N]
R278  0  [RESC1005X40N]
U6  MAX98089  [QFN40P700X700X80-57T560X560N]  (parts A,B of 2)
U17  AP2202  [SOT95P280X145-5N]
U22  SI2323DS-T1-E3  [SOT95P240X110_GSD-3N]

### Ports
AUD_I2C_SCL (bidir), AUD_I2C_SDA (bidir), AUD_INT# (bidir), AUD_PWR/IO28 (bidir), JTAG_TCK/SAI2_RX_DATA (bidir), JTAG_TDI/SAI2_TX_BCLK (bidir), JTAG_TDO/SAI2_TX_SYNC (bidir), JTAG_TMS/SAI2_MCLK (bidir), JTAG_TRST_N/SAI2_TX_DATA (bidir), LINE_IN_A_L (bidir), LINE_IN_A_R (bidir), LINE_OUT_L (bidir), LINE_OUT_R (bidir), MIC_N (bidir), MIC_P (bidir), PCM_CLK (bidir), PCM_IN (bidir), PCM_OUT (bidir), PCM_SYNC (bidir)

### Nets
1V8_CODEC: C91.2 C92.1 C93.1 C94.1 C118.2 R91.2 U6.25(PVDD) U6.50(AVDD) U6.53(DVDD) U17.5(VOUT)
3V3: R93.1 R128.1 R132.1 R206.1 U22.S
3V3_CODEC: C87.1 C89.1 C98.2 C102.1 C103.1 C129.2 C149.2 R206.2 U6.6(DVDDS1) U6.18(SPKRVDD) U6.19(SPKLVDD) U6.55(DVDDS2) U17.1(VIN) U17.3(EN) U22.D
GND: C87.2 C89.2 C90.1 C91.1 C92.2 C93.2 C94.2 C95.1 C96.2 C97.1 C98.1 C102.2 C103.2 C118.1 C129.1 C131.2 C134.2 C137.2 C138.2 C139.2 C140.2 C143.2 J22.1 NT1.2 Q4.S R92.1 U6.3(DGND) U6.16(SPKRGND) U6.21(SPKLGND) U6.30(HPGND) U6.47(AGND) U6.57(EP) U17.2(GND)
AUD_I2C_SCL: U6.51(SCL) ; port AUD_I2C_SCL
AUD_I2C_SDA: U6.52(SDA) ; port AUD_I2C_SDA
AUD_INT#: R93.2 U6.56(IRQ#) ; port AUD_INT#
AUD_PWR/IO28: Q4.G R132.2 ; port AUD_PWR/IO28
JTAG_TCK/SAI2_RX_DATA: R191.1 ; port JTAG_TCK/SAI2_RX_DATA
JTAG_TDI/SAI2_TX_BCLK: R131.1 ; port JTAG_TDI/SAI2_TX_BCLK
JTAG_TDO/SAI2_TX_SYNC: R189.1 ; port JTAG_TDO/SAI2_TX_SYNC
JTAG_TMS/SAI2_MCLK: R94.1 ; port JTAG_TMS/SAI2_MCLK
JTAG_TRST_N/SAI2_TX_DATA: R190.1 ; port JTAG_TRST_N/SAI2_TX_DATA
LINE_IN_A_L: L21.1 ; port LINE_IN_A_L
LINE_IN_A_R: L20.1 ; port LINE_IN_A_R
LINE_IN_B_L: J33.6 L23.1
LINE_IN_B_R: J33.5 L22.1
LINE_OUT_L: U6.23(RECN/LOUTR/RXINN) ; port LINE_OUT_L
LINE_OUT_R: U6.24(RECP/LOUTL/RXINP) ; port LINE_OUT_R
MIC_BIAS: C132.2 L19.2 R196.1 U6.45(JACKSNS)
MIC_N: L24.1 ; port MIC_N
MIC_P: L19.1 ; port MIC_P
PCM_CLK: R192.1 ; port PCM_CLK
PCM_IN: R195.1 ; port PCM_IN
PCM_OUT: R194.1 ; port PCM_OUT
PCM_SYNC: R193.1 ; port PCM_SYNC
SPKL_N: R276.1 U6.22(SPKLN)
SPKL_P: R255.1 U6.20(SPKLP)
SPKR_N: R278.1 U6.15(SPKRN)
SPKR_P: R277.1 U6.17(SPKRP)
NetC88_1: C88.1 U6.27(CIN)
NetC88_2: C88.2 U6.26(C1P)
NetC90_2: C90.2 U6.32(HPVDD)
NetC95_2: C95.2 U6.31(HPVSS)
NetC96_1: C96.1 U6.48(REF)
NetC97_2: C97.2 U6.49(REG)
NetC131_1: C131.1 R196.2 U6.44(MICBIAS)
NetC132_1: C132.1 U6.42(MIC2P)
NetC133_1: C133.1 U6.43(MIC2N)
NetC133_2: C133.2 L24.2
NetC134_1: C134.1 C135.1 U6.39(INA1/EXTMICP)
NetC135_2: C135.2 L20.2
NetC136_1: C136.1 C138.1 U6.38(INA2/EXTMICN)
NetC136_2: C136.2 L21.2
NetC137_1: C137.1 R197.1 U6.35(HPR)
NetC139_1: C139.1 R198.1 U6.33(HPL)
NetC140_1: C140.1 C141.1 U6.37(INB1)
NetC141_2: C141.2 L22.2
NetC142_1: C142.1 C143.1 U6.36(INB2)
NetC142_2: C142.2 L23.2
NetC149_1: C149.1 Q4.D R128.2 U22.G
NetJ22_2: J22.2 R197.2
NetJ22_3: J22.3 R198.2
NetJ33_1: J33.1 R255.2
NetJ33_2: J33.2 R276.2
NetJ33_3: J33.3 R277.2
NetJ33_4: J33.4 R278.2
NetNT1_1: NT1.1 U6.34(HPSNS)
NetR91_1: R91.1 R92.2 U17.4(ADJ)
NetR94_2: R94.2 U6.5(MCLK)
NetR131_2: R131.2 U6.8(BCLKS1)
NetR189_2: R189.2 U6.10(LRCLKS1)
NetR190_2: R190.2 U6.9(SDINS1)
NetR191_2: R191.2 U6.7(SDOUTS1)
NetR192_2: R192.2 U6.2(BCLKS2)
NetR193_2: R193.2 U6.4(LRCLKS2)
NetR194_2: R194.2 U6.54(SDINS2)
NetR195_2: R195.2 U6.1(SDOUTS2)

Not connected (* = marked no-connect by the designer): J22 4* 5*; U6 11(NC)* 12(NC)* 13(NC)* 14(NC)* 28(NC)* 29(NC)* 40(MIC1P/DIGMICDATA)* 41(MIC1N/DIGMICCLK)* 46(NC)*

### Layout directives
differential pair: MIC_N, MIC_P, SPKL_N, SPKL_P, SPKR_N, SPKR_P

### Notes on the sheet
- AUDIO
- WARNING:
  Right and left channels are inverted on J22.
  J22.2 should be the left channel and J22.3 should be right channel.
- Enabled by default
- VOUT = 1.25V x (1+R92/R91)
  = 1.25V x (1+12K/27K)
  = 1.8V

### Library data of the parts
C87 C89 = 1000918: CAP CER 0.1UF 50V 10% X7R 0402; Part_Type: Capacitor; Manufacturer: TDK Corporation; Manufacturer_Part_Number: C1005X7R1H104K050BB; Digi_PN: 14050715; Component_Life_Cycle_State: Reviewed; Area: 0.95; Project: DTM3.0
C88 C90 C92-C95 C97 C102 C103 = 1001167: as C18 on sheet 06 - Ethernet
C91 C98 = 1000111: CAP CER 10UF 16V 10% X5R 0805; Part_Type: Capacitor; Manufacturer: Murata; Manufacturer_Part_Number: GRM21BR61C106KE15L; Digi_PN: 14050701; Component_Life_Cycle_State: Proven; Area: 3.99; Project: Adjustable Foundation; Tolerance: 10
C96 = 1000970: CAP CER 2.2UF 6.3V 20% X5R 0402; Part_Type: Capacitor; Manufacturer: TDK Corporation; Manufacturer_Part_Number: C1005X5R0J225M050BC; Manufacturer_Alt_1: Taiyo Yuden; Manufacturer_Alt_1_Part_Number: JMK105BJ225MV-F; Note: 14050756 = Digi No. for GE WDNU; Digi_PN: 14050493; Component_Life_Cycle_State: Reviewed; Area: 0,5; Project: ConnectCore i.MX6 module; Tolerance: 20
C118 = 1001303: CAP CER 2.2UF 16V 10% X5R 0603; Part_Type: Capacitor; Manufacturer: TDK Corporation; Manufacturer_Part_Number: C1608X5R1C225K080AB; Digi_PN: 14050730; Component_Life_Cycle_State: Reviewed; Area: 2,27; Project: Pinnacle
C129 C131-C133 C135 C136 C141 C142 = 1000073: CAP CER 1UF 6.3V 20% X5R 0402; Part_Type: Capacitor; Manufacturer: Murata; Manufacturer_Part_Number: GRM155R60J105ME19D; Digi_PN: 14050543; Component_Life_Cycle_State: Proven; Area: 0.95; Project: Adjustable Foundation
C134 C137-C140 C143 = 1001541: CAP CER 10PF 50V 5% NP0 0402; Part_Type: Capacitor; Manufacturer: Murata; Manufacturer_Part_Number: GRM1555C1H100JA01D; Note: 14050750 = Digi No. for GE WDNU; Digi_PN: 14050362; Component_Life_Cycle_State: Reviewed; Area: 0,95; Project: KITT v0.4; Tolerance: 5; Temp_Coef: C0G, NP0
C149 = 1000067: as C26 on sheet 06 - Ethernet
J22 = 1001133: CONN JACK STEREO 5POS 3.5MM SMD; Part_Type: Connector; Manufacturer: CUI Inc.; Manufacturer_Part_Number: SJ1-3515-SMT; Digi_PN: MA02822; Component_Life_Cycle_State: Reviewed; Area: 114; Project: CCWMX6_SBC board
J33 = 1001138: CONN HEADER 6POS 1.25MM VERT TIN; Part_Type: Connector; Manufacturer: Molex; Digi_PN: 18050345; Component_Life_Cycle_State: Reviewed; Area: 29.6; Project: CCWMX6_SBC board
L19-L24 = 1002041: FERRITE BEAD 1.8 KOHM 0402 1LN; Manufacturer: Murata; Manufacturer_Part_Number: BLM15HD182SN1D; Digi_PN: 21000461; Component_Life_Cycle_State: Reviewed; Area: 2.2; Project: iMX6UL+PMIC
NT1 = CAD0044: NET TIE FOR I.MX6x SOM; Component_Life_Cycle_State: Created; Area: 0,039; Project: ConnectCore i.MX6x SOM
Q4 = 1000715: as Q7 on sheet 06 - Ethernet
R91 = 1001153: RES 27.0K OHM 1/16W 1% 0402 SMD; Part_Type: Resistor; Manufacturer: Yageo; Manufacturer_Part_Number: RC0402FR-0727KL; Digi_PN: 13050609; Component_Life_Cycle_State: Reviewed; Area: 0,95; Project: CCWMX6_SBC board
R92 = 1001200: RES 12.0K OHM 1/10W 1% 0603 SMD; Part_Type: Resistor; Manufacturer: Yageo; Manufacturer_Part_Number: RC0603FR-0712KL; Digi_PN: 13050531; Component_Life_Cycle_State: Reviewed; Area: 2,5; Project: LuCoV2; Power_WV_SRF: 100; Tolerance: 1
R93 R128 = 1000537: as R36 on sheet 05 - JTAG, SWD, Console, UART, IO expander
R94 R131 R189-R195 R197 R198 R255 R276-R278 = 1000076: as R81 on sheet 05 - JTAG, SWD, Console, UART, IO expander
R132 = 1000480: as R51 on sheet 06 - Ethernet
R196 = 1001156: RES 2.20K OHM 1/16W 1% 0402 SMD; Part_Type: Resistor; Manufacturer: Yageo; Manufacturer_Part_Number: RC0402FR-072K2L; Note: 13051099 = Digi No. for GE WDNU; Digi_PN: 13050699; Component_Life_Cycle_State: Reviewed; Area: 0,95; Project: CCWMX6_SBC board
R206 = 1000208: as R27 on sheet 06 - Ethernet
U6 = 1002001: IC CODEC AUDIO FLEXSOUND 56TQFN; Manufacturer: Maxim; Manufacturer_Part_Number: MAX98089ETN+T; Component_Life_Cycle_State: Reviewed; Area: 49; Project: iMX6UL+PMIC; Digi_PN: 16052036
U17 = 1001979: IC REG LDO ADJ 0.15A SOT25; Part_Type: Regulator; Manufacturer: Diodes, Inc.; Manufacturer_Part_Number: AP2202K-ADJTRG1; Digi_PN: 17050874; Component_Life_Cycle_State: Created; Area: 8,9; Project: iMX6UL+PMIC
U22 = 1001163: as U8 on sheet 06 - Ethernet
